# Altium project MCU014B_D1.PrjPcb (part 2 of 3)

## Sheet MCU014B_D1_EngineArea.SchDoc
size 558 x 431 mm; Date: Not shown in title block; ApprovedBy: Not shown in title block; CheckedBy: Not shown in title block; Author: Not shown in title block; CompanyName: Not shown in title block; DrawnBy: Vince Rodriguez; Engineer: Vince Rodriguez; Organization: Not shown in title block; Address1: Not shown in title block; Address2: Not shown in title block; Address3: Not shown in title block; Address4: Not shown in title block; DocumentNumber: 3; Revision: Use project parameter SCH_Rev; SheetNumber: 3; SheetTotal: 7; PageSetup: Record=PageOptions¦CenterHorizontal=True¦CenterVertical=True¦PrintScale=1.00¦XCorrection=1.00¦YCorrection=1.00¦PrintKind=0¦BorderSize=5000000¦LeftOffset=0¦BottomOffset=0¦Orientation=2¦PaperLength=1000¦PaperWidth=1000¦Scale=100¦PaperSource=15¦PrintQuality=600¦MediaType=1¦DitherType=10¦PaperKind=Letter¦PrintScaleMode=1
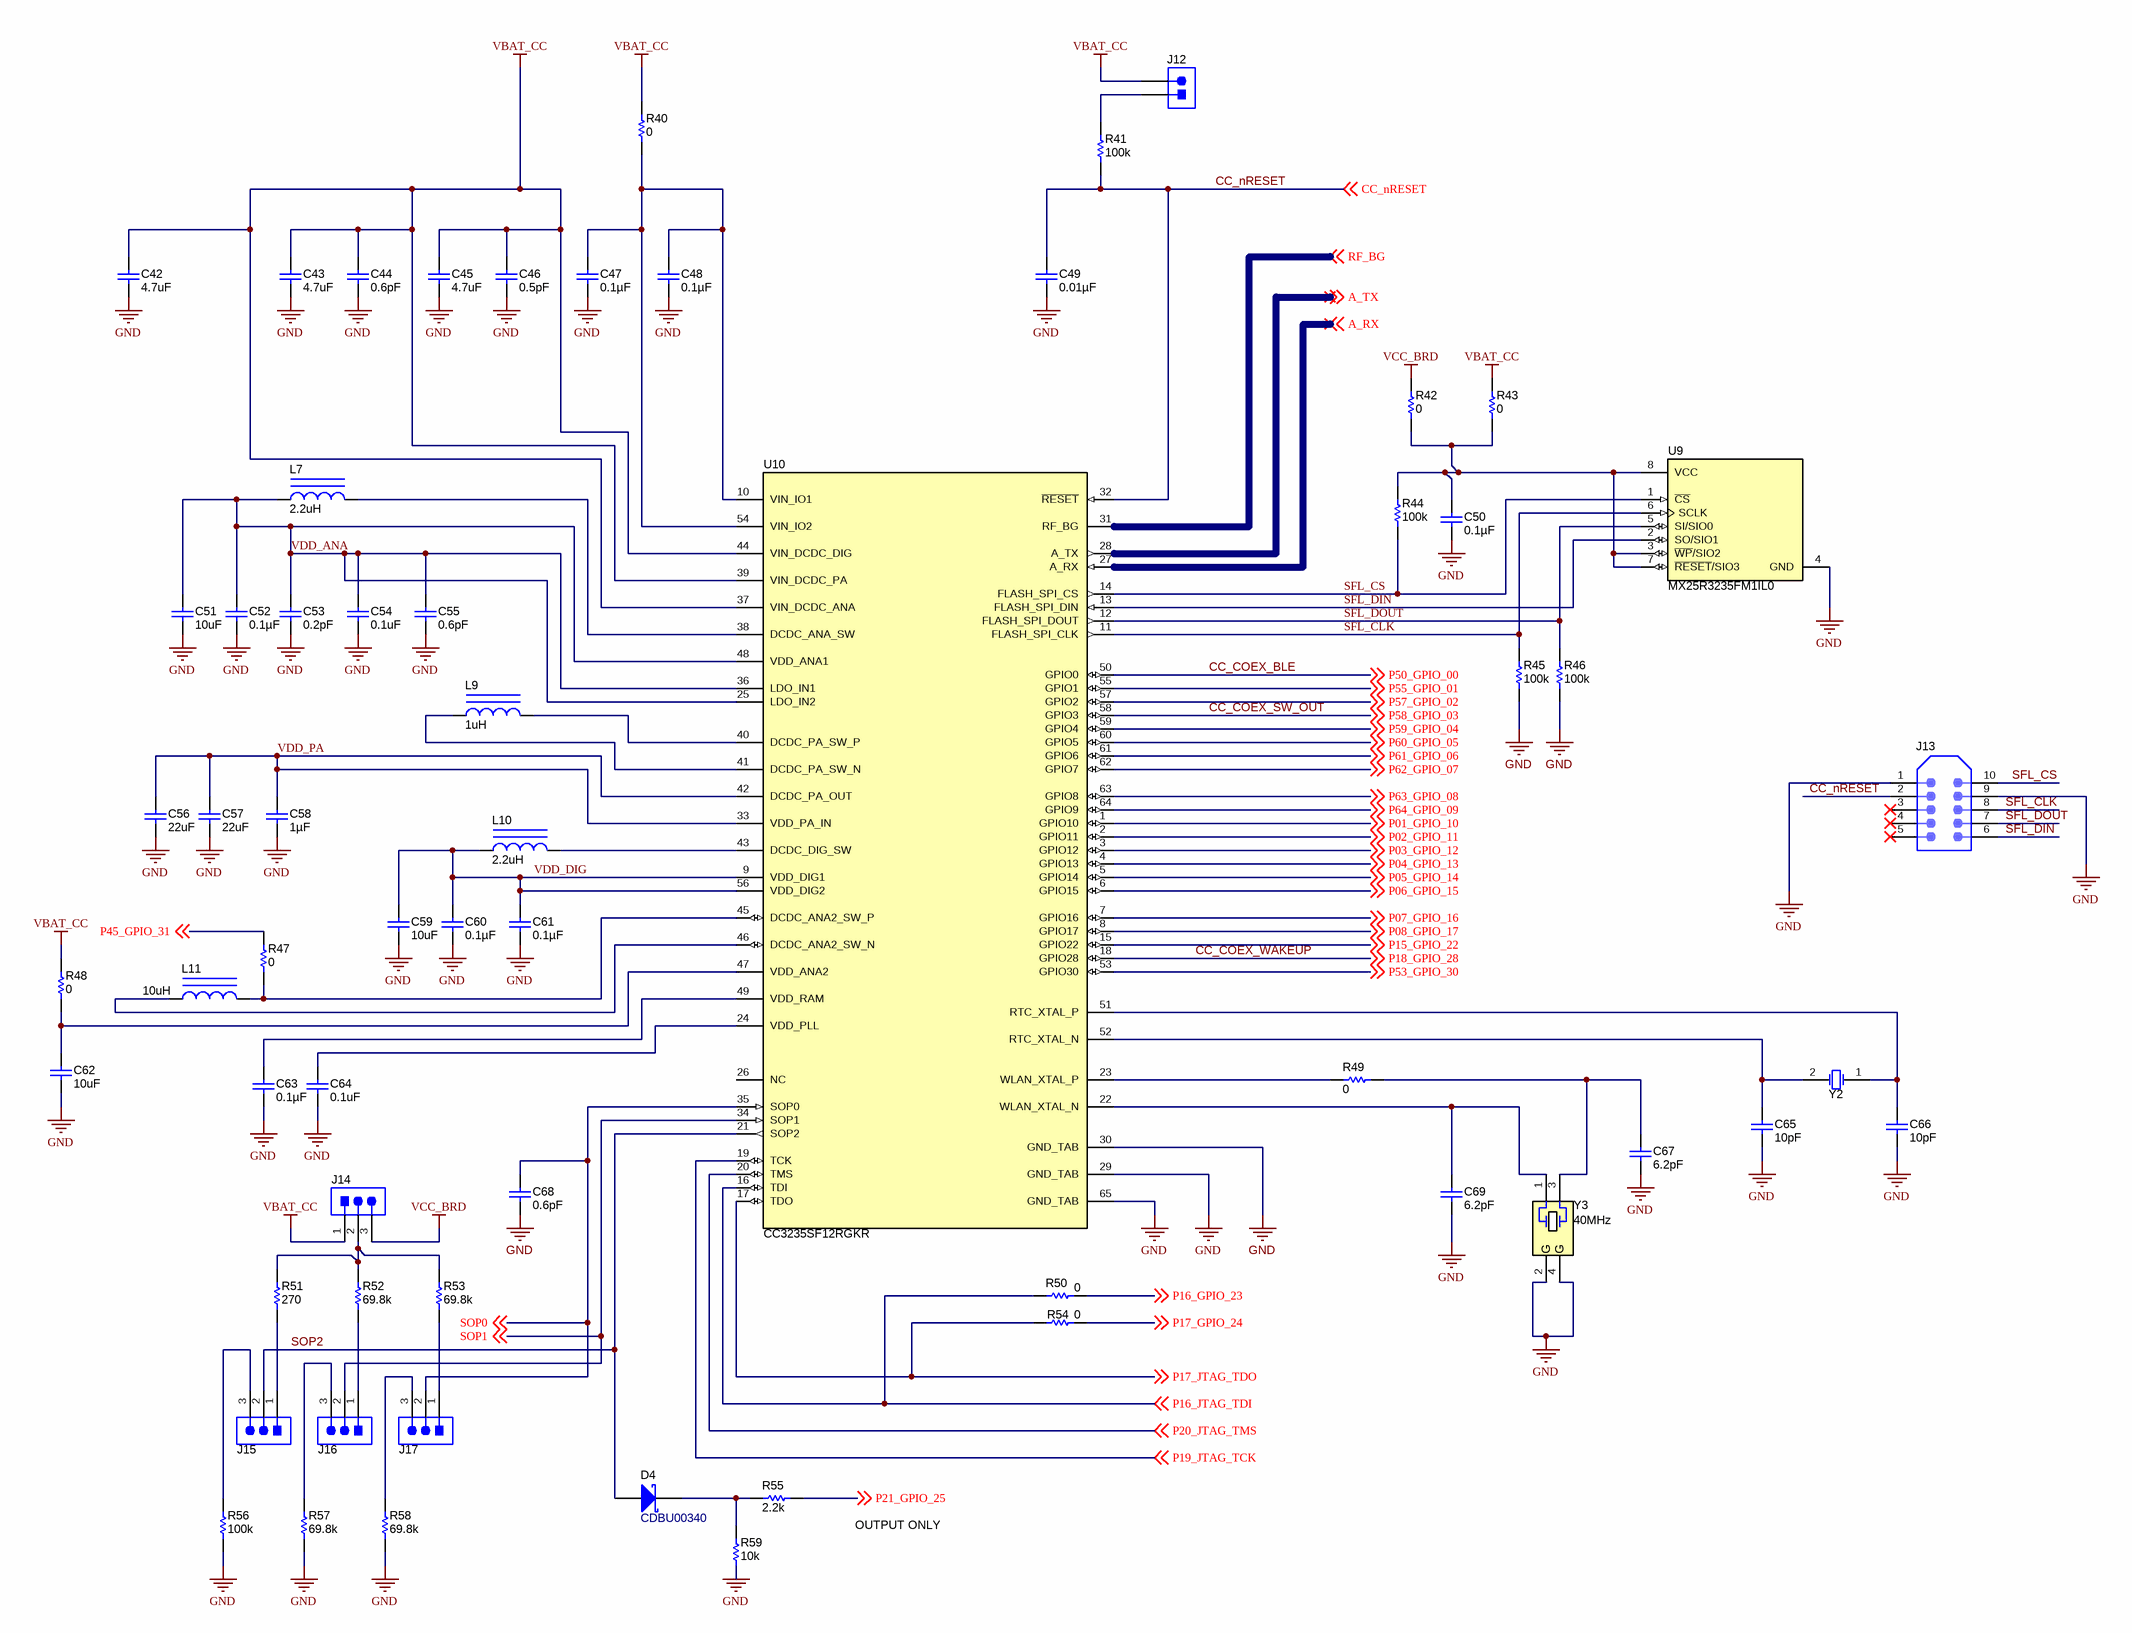
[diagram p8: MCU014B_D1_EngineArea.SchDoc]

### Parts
C42  ValueDisplayed: 4.7uF  [0402]  (hidden comment: CMP-0064972-2)
C43  ValueDisplayed: 4.7uF  [0402]  (hidden comment: CMP-0064972-2)
C44  ValueDisplayed: 0.6pF  [0201_033]  (hidden comment: GJM0335C1ER60BB01D)
C45  ValueDisplayed: 4.7uF  [0402]  (hidden comment: CMP-0064972-2)
C46  ValueDisplayed: 0.5pF  [0201_033]  (hidden comment: GJM0335C1ER50BB01D)
C47  ValueDisplayed: 0.1µF  [0402S]  (hidden comment: CL05B104KO5NNNC)
C48  ValueDisplayed: 0.1µF  [0402S]  (hidden comment: CL05B104KO5NNNC)
C49  ValueDisplayed: 0.01µF  [0402S]  (hidden comment: 0402B103K500CT)
C50  ValueDisplayed: 0.1µF  [0402S]  (hidden comment: CL05B104KO5NNNC)
C51  ValueDisplayed: 10uF  [0603]  (hidden comment: CMP-0064953-4)
C52  ValueDisplayed: 0.1µF  [0402S]  (hidden comment: CL05B104KO5NNNC)
C53  ValueDisplayed: 0.2pF  [0201_033]  (hidden comment: GJM0335C1ER20BB01D)
C54  ValueDisplayed: 0.1uF  [0201]  (hidden comment: CL03A104KP3NNNC)
C55  ValueDisplayed: 0.6pF  [0201_033]  (hidden comment: GJM0335C1ER60BB01D)
C56  ValueDisplayed: 22uF  [0603]  (hidden comment: CMP-0064952-4)
C57  ValueDisplayed: 22uF  [0603]  (hidden comment: CMP-0064952-4)
C58  ValueDisplayed: 1µF  [0402S]  (hidden comment: CL05A105MP5NNNC)
C59  ValueDisplayed: 10uF  [0603]  (hidden comment: CMP-0064953-4)
C60  ValueDisplayed: 0.1µF  [0402S]  (hidden comment: CL05B104KO5NNNC)
C61  ValueDisplayed: 0.1µF  [0402S]  (hidden comment: CL05B104KO5NNNC)
C62  ValueDisplayed: 10uF  [0603]  (hidden comment: CMP-0064953-4)
C63  ValueDisplayed: 0.1µF  [0402S]  (hidden comment: CL05B104KO5NNNC)
C64  ValueDisplayed: 0.1uF  [0201]  (hidden comment: CMP-0009655-3)
C65  ValueDisplayed: 10pF  [0402S]  (hidden comment: 0402N100J500CT)
C66  ValueDisplayed: 10pF  [0402S]  (hidden comment: 0402N100J500CT)
C67  ValueDisplayed: 6.2pF  [0402S]  (hidden comment: 0402N6R2C500CT)
C68  ValueDisplayed: 0.6pF  [0201_033]  (hidden comment: GJM0335C1ER60BB01D)
C69  ValueDisplayed: 6.2pF  [0402S]  (hidden comment: 0402N6R2C500CT)
D4  CDBU00340  [SOD-523F]
J12  CMP-0054794-1  [WURTH_61300211121]  (value not drawn)
J13  TC2050-IDC-NL-FP  [Tag_TC2050-NL]  (value not drawn)  (no BOM)
J14  CMP-0054796-1  [WURTH_61300311121]  (value not drawn)
J15  CMP-0054796-1  [WURTH_61300311121]  (value not drawn)
J16  CMP-0054796-1  [WURTH_61300311121]  (value not drawn)
J17  CMP-0054796-1  [WURTH_61300311121]  (value not drawn)
L7  ValueDisplayed: 2.2uH  [LQM2MPN_G0]  (hidden comment: CMP-0058761-1)
L9  ValueDisplayed: 1uH  [1008]  (hidden comment: CMP-0058750-1)
L10  ValueDisplayed: 2.2uH  [LQM2MPN_G0]  (hidden comment: CMP-0058761-1)
L11  ValueDisplayed: 10uH  [MLP2520S-M]  (hidden comment: CMP-0062710-1)
R40  ValueDisplayed: 0  [0603]  (hidden comment: CMP-0025874-3)
R41  ValueDisplayed: 100k  [0402]  (hidden comment: CMP-0026823-3)
R42  ValueDisplayed: 0  [0402]  (hidden comment: CMP-0026992-2)
R43  ValueDisplayed: 0  [0402]  (hidden comment: CMP-0026992-2)
R44  ValueDisplayed: 100k  [0402]  (hidden comment: CMP-0026823-3)
R45  ValueDisplayed: 100k  [0402]  (hidden comment: CMP-0026823-3)
R46  ValueDisplayed: 100k  [0402]  (hidden comment: CMP-0026823-3)
R47  ValueDisplayed: 0  [0402]  (hidden comment: CMP-0026992-2)
R48  ValueDisplayed: 0  [0402]  (hidden comment: CMP-0026992-2)
R49  ValueDisplayed: 0  [0402]  (hidden comment: CMP-0026992-2)
R50  ValueDisplayed: 0  [0402]  (hidden comment: CMP-0026992-2)
R51  ValueDisplayed: 270  [0402]  (hidden comment: CMP-0026886-3)
R52  ValueDisplayed: 69.8k  [0402]  (hidden comment: CMP-0026510-2)
R53  ValueDisplayed: 69.8k  [0402]  (hidden comment: CMP-0026510-2)
R54  ValueDisplayed: 0  [0402]  (hidden comment: CMP-0026992-2)
R55  ValueDisplayed: 2.2k  [0402]  (hidden comment: CMP-0026890-5)
R56  ValueDisplayed: 100k  [0402]  (hidden comment: CMP-0026823-3)
R57  ValueDisplayed: 69.8k  [0402]  (hidden comment: CMP-0026510-2)
R58  ValueDisplayed: 69.8k  [0402]  (hidden comment: CMP-0026510-2)
R59  ValueDisplayed: 10k  [0402]  (hidden comment: CMP-0026825-5)
U9  PartNumber: MX25R3235FM1IL0  [SOP-8_150MIL]  (hidden comment: CMP-0004903-1)
U10  CC3235SF12RGKR  [RGK0064B]
Y2  CMP-0004575-3  [XTAL_ABS07]  (value not drawn)
Y3  Frequency_Fixed: 40MHz  [TXC_8Y]  (hidden comment: 8Y40072002)

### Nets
GND: C42.2 C43.2 C44.2 C45.2 C46.2 C47.2 C48.2 C49.2 C50.2 C51.2 C52.2 C53.2 C54.2 C55.2 C56.2 C57.2 C58.2 C59.2 C60.2 C61.2 C62.2 C63.2 C64.2 C65.2 C66.2 C67.2 C68.2 C69.2 J13.1 J13.9 R45.2 R46.2 R56.2 R57.2 R58.2 R59.2 U9.4(GND) U10.29(GND_TAB) U10.30(GND_TAB) U10.65(GND_TAB) Y3.2(GND) Y3.4(GND)
VBAT_CC: C42.1 C43.1 C44.1 C45.1 C46.1 J12.2 J14.1 R40.2 R43.2 R48.2 U10.37(VIN_DCDC_ANA) U10.39(VIN_DCDC_PA) U10.44(VIN_DCDC_DIG)
VCC_BRD: J14.3 R42.2
A_RX: U10.27(A_RX) ; off-sheet A_RX
A_TX: U10.28(A_TX) ; off-sheet A_TX
CC_COEX_BLE: U10.50(GPIO0) ; off-sheet P50_GPIO_00  [also labelled P50_GPIO_00]
CC_COEX_SW_OUT: U10.58(GPIO3) ; off-sheet P58_GPIO_03  [also labelled P58_GPIO_03]
CC_COEX_WAKEUP: U10.18(GPIO28) ; off-sheet P18_GPIO_28  [also labelled P18_GPIO_28]
CC_nRESET: C49.1 J13.2 R41.2 U10.32(~{RESET}) ; off-sheet CC_nRESET
P01_GPIO_10: U10.1(GPIO10) ; off-sheet P01_GPIO_10
P02_GPIO_11: U10.2(GPIO11) ; off-sheet P02_GPIO_11
P03_GPIO_12: U10.3(GPIO12) ; off-sheet P03_GPIO_12
P04_GPIO_13: U10.4(GPIO13) ; off-sheet P04_GPIO_13
P05_GPIO_14: U10.5(GPIO14) ; off-sheet P05_GPIO_14
P06_GPIO_15: U10.6(GPIO15) ; off-sheet P06_GPIO_15
P07_GPIO_16: U10.7(GPIO16) ; off-sheet P07_GPIO_16
P08_GPIO_17: U10.8(GPIO17) ; off-sheet P08_GPIO_17
P15_GPIO_22: U10.15(GPIO22) ; off-sheet P15_GPIO_22
P16_GPIO_23: R50.2 ; off-sheet P16_GPIO_23
P16_JTAG_TDI: R50.1 U10.16(TDI) ; off-sheet P16_JTAG_TDI
P17_GPIO_24: R54.2 ; off-sheet P17_GPIO_24
P17_JTAG_TDO: R54.1 U10.17(TDO) ; off-sheet P17_JTAG_TDO
P19_JTAG_TCK: U10.19(TCK) ; off-sheet P19_JTAG_TCK
P20_JTAG_TMS: U10.20(TMS) ; off-sheet P20_JTAG_TMS
P21_GPIO_25: R55.2 ; off-sheet P21_GPIO_25
P45_GPIO_31: R47.1 ; off-sheet P45_GPIO_31
P53_GPIO_30: U10.53(GPIO30) ; off-sheet P53_GPIO_30
P55_GPIO_01: U10.55(GPIO1) ; off-sheet P55_GPIO_01
P57_GPIO_02: U10.57(GPIO2) ; off-sheet P57_GPIO_02
P59_GPIO_04: U10.59(GPIO4) ; off-sheet P59_GPIO_04
P60_GPIO_05: U10.60(GPIO5) ; off-sheet P60_GPIO_05
P61_GPIO_06: U10.61(GPIO6) ; off-sheet P61_GPIO_06
P62_GPIO_07: U10.62(GPIO7) ; off-sheet P62_GPIO_07
P63_GPIO_08: U10.63(GPIO8) ; off-sheet P63_GPIO_08
P64_GPIO_09: U10.64(GPIO9) ; off-sheet P64_GPIO_09
RF_BG: U10.31(RF_BG) ; off-sheet RF_BG
SFL_CLK: J13.8 R45.1 U9.6(SCLK) U10.11(FLASH_SPI_CLK)
SFL_CS: J13.10 R44.2 U9.1(~{CS}) U10.14(FLASH_SPI_CS)
SFL_DIN: J13.6 U9.2(SO/SIO1) U10.13(FLASH_SPI_DIN)
SFL_DOUT: J13.7 R46.1 U9.5(SI/SIO0) U10.12(FLASH_SPI_DOUT)
SOP0: C68.1 J17.2 U10.35(SOP0) ; off-sheet SOP0
SOP1: J16.2 U10.34(SOP1) ; off-sheet SOP1
SOP2: D4.2(A) J15.2 U10.21(SOP2)
VDD_ANA: C51.1 C52.1 C53.1 C54.1 C55.1 L7.1 U10.25(LDO_IN2) U10.36(LDO_IN1) U10.48(VDD_ANA1)
VDD_DIG: C59.1 C60.1 C61.1 L10.1 U10.9(VDD_DIG1) U10.56(VDD_DIG2)
VDD_PA: C56.1 C57.1 C58.1 U10.33(VDD_PA_IN) U10.42(DCDC_PA_OUT)
NetC47_1: C47.1 C48.1 R40.1 U10.10(VIN_IO1) U10.54(VIN_IO2)
NetC50_1: C50.1 R42.1 R43.1 R44.1 U9.3(~{WP}/SIO2) U9.7(~{RESET}/SIO3) U9.8(VCC)
NetC62_1: C62.1 R48.1 U10.47(VDD_ANA2)
NetC63_1: C63.1 U10.49(VDD_RAM)
NetC64_1: C64.1 U10.24(VDD_PLL)
NetC65_1: C65.1 U10.52(RTC_XTAL_N) Y2.2(OSC2)
NetC66_1: C66.1 U10.51(RTC_XTAL_P) Y2.1(OSC1)
NetC67_1: C67.1 R49.1 Y3.3
NetC69_1: C69.1 U10.22(WLAN_XTAL_N) Y3.1
NetD4_1: D4.1(K) R55.1 R59.1
NetJ12_1: J12.1 R41.1
NetJ14_2: J14.2 R51.1 R52.1 R53.1
NetJ15_1: J15.1 R51.2
NetJ15_3: J15.3 R56.1
NetJ16_1: J16.1 R52.2
NetJ16_3: J16.3 R57.1
NetJ17_1: J17.1 R53.2
NetJ17_3: J17.3 R58.1
NetL7_2: L7.2 U10.38(DCDC_ANA_SW)
NetL9_1: L9.1 U10.41(DCDC_PA_SW_N)
NetL9_2: L9.2 U10.40(DCDC_PA_SW_P)
NetL10_2: L10.2 U10.43(DCDC_DIG_SW)
NetL11_1: L11.1 U10.46(DCDC_ANA2_SW_N)
NetL11_2: L11.2 R47.2 U10.45(DCDC_ANA2_SW_P)
NetR49_2: R49.2 U10.23(WLAN_XTAL_P)

Not connected (* = marked no-connect by the designer): J13 3* 4* 5*; U10 26(NC)

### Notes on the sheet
- OUTPUT ONLY

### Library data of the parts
C42 C43 C45 = CMP-0064972-2: CAP, CERM, 4.7 uF, 6.3 V,+/- 20%, X6S, 0402; PartNumber: JMK105BC6475MV-F; Manufacturer: Taiyo Yuden; Alternate PartNumber: CL05A475MQ5NRNC; Alternate Manufacturer: SAMSUNG; Polarized: N; CompType: Capacitor; Value: 4.7uF; U/M: EA; Cap_F: 4.7µF; Value1: Unknown; VDC_V: 6.3V; TaMin_C: -55°C; TaMax_C: 105°C; SizeArea_mm2: 0.5; SizeAreaWB_mm2: 3; SizeX_mm: 1; SizeZ_mm: 0.6; AEC Category: Q200
C44 C55 C68 = CMP-0085407-1: CAP, CERM, 0.6pF, 25 V,+/- 16%, C0G/NP0, 0201; Manufacturer: MuRata; Polarized: N; U/M: EA; VDC_V: 25V; TaMin_C: -55°C; TaMax_C: 125°C; Cap_Case: 0201; SizeArea_mm2: 0.18; SizeAreaWB_mm2: 2.08; SizeX_mm: 0.6; SizeY_mm: 0.3; SizeZ_mm: 0.33; AEC Category: Q200
C46 = CMP-0085408-1: CAP, CERM, 0.5 pF, 25 V,+/- 20%, C0G/NP0, 0201; Manufacturer: MuRata; Polarized: N; Value: 0.5pF; U/M: EA; VDC_V: 25V; TaMin_C: -55°C; TaMax_C: 125°C; Cap_Case: 0201; SizeArea_mm2: 0.18; SizeAreaWB_mm2: 2.08; SizeX_mm: 0.6; SizeY_mm: 0.3; SizeZ_mm: 0.33; AEC Category: Q200
C47 C48 C50 C52 C60 C61 C63 = CMP-0085850-1: CAP, CERM, 0.1 µF, 16 V,+/- 10%, X7R, 0402; Manufacturer: Walsin; Alternate PartNumber: C1005X5R1A104K050BA; Polarized: N; Value: 0.1uF; U/M: EA; Cap_F: 100nF; VDC_V: 16V; TaMin_C: -55°C; TaMax_C: 125°C; Cap_Case: 0402; SizeArea_mm2: 0.5; SizeAreaWB_mm2: 3; SizeX_mm: 1; SizeZ_mm: 0.6; AEC Category: Q200
C49 = CMP-0085842-1: CAP, CERM, 0.01 µF, 50 V,+/- 10%, X7R, 0402; Manufacturer: Walsin; Alternate PartNumber: GRM155R71E103KA01D; Polarized: N; Value: 0.01uF; U/M: EA; Cap_F: 10nF; VDC_V: 50V; TaMin_C: -55°C; TaMax_C: 125°C; Cap_Case: 0402; SizeArea_mm2: 0.5; SizeAreaWB_mm2: 3; SizeX_mm: 1; SizeZ_mm: 0.6; AEC Category: Q200
C51 C59 C62 = CMP-0064953-4: CAP, CERM, 10 uF, 10 V,+/- 20%, X6S, 0603; PartNumber: LMK107BC6106MA-T; Manufacturer: Taiyo Yuden; Alternate PartNumber: CL10A106MP8NNNC; Alternate Manufacturer: SAMSUNG; Polarized: N; CompType: Capacitor; Value: 10uF; U/M: EA; Cap_F: 10µF; Value1: Unknown; VDC_V: 10V; TaMin_C: -55°C; TaMax_C: 105°C; SizeArea_mm2: 1.28; SizeAreaWB_mm2: 4.68; SizeX_mm: 1.6; SizeY_mm: 0.8; SizeZ_mm: 1; AEC Category: Q200
C53 = CMP-0085602-1: CAP, CERM, 0.2pF, 25 V,+/- 50%, C0G/NP0, 0201; Manufacturer: MuRata; Polarized: N; U/M: EA; VDC_V: 25V; TaMin_C: -55°C; TaMax_C: 125°C; Cap_Case: 0201; SizeArea_mm2: 0.18; SizeAreaWB_mm2: 2.08; SizeX_mm: 0.6; SizeY_mm: 0.3; SizeZ_mm: 0.33; AEC Category: Q200
C54 = CMP-0009655-3: CAP, CERM, 0.1 uF, 10 V, +/- 10%, X5R, 0201; Manufacturer: Samsung Electro-Mechanics; Polarized: N; Value: 0.1uF; U/M: EA; Cap_F: 100nF; Value1: Unknown; VDC_V: 10V; TaMin_C: -55°C; TaMax_C: 85°C; SizeArea_mm2: 0.18; SizeAreaWB_mm2: 2.08; SizeX_mm: 0.6; SizeY_mm: 0.3; SizeZ_mm: 0.26; AEC Category: Q200
C56 C57 = CMP-0064952-4: CAP, CERM, 22 uF, 4 V,+/- 20%, X6S, 0603; PartNumber: GRM188C80G226ME15J; Manufacturer: MuRata; Alternate PartNumber: CL10A226MQ8NRNC; Alternate Manufacturer: SAMSUNG; Polarized: N; CompType: Capacitor; Value: 22uF; U/M: EA; Cap_F: 22µF; Value1: Unknown; VDC_V: 4V; TaMin_C: -55°C; TaMax_C: 105°C; SizeArea_mm2: 1.28; SizeAreaWB_mm2: 4.68; SizeX_mm: 1.6; SizeY_mm: 0.8; SizeZ_mm: 1; AEC Category: Q200
C58 = CMP-0085849-1: CAP, CERM, 1 µF, 10 V,+/- 20%, X5R, 0402; Manufacturer: Walsin; Alternate PartNumber: GRM155C81A105KA12D; Polarized: N; Value: 1uF; U/M: EA; VDC_V: 10V; TaMin_C: -55°C; TaMax_C: 85°C; Cap_Case: 0402; SizeArea_mm2: 0.5; SizeAreaWB_mm2: 3; SizeX_mm: 1; SizeZ_mm: 0.6; AEC Category: Q200
C64 = CMP-0009655-3: CAP, CERM, 0.1 uF, 10 V, +/- 10%, X5R, 0201; PartNumber: CL03A104KP3NNNC; Manufacturer: Samsung Electro-Mechanics; Polarized: N; Value: 0.1uF; U/M: EA; Cap_F: 100nF; Value1: Unknown; VDC_V: 10V; TaMin_C: -55°C; TaMax_C: 85°C; SizeArea_mm2: 0.18; SizeAreaWB_mm2: 2.08; SizeX_mm: 0.6; SizeY_mm: 0.3; SizeZ_mm: 0.26; AEC Category: Q200
C65 C66 = CMP-0085843-1: CAP, CERM, 10 pF, 50 V,+/- 5%, C0G/NP0, 0402; Manufacturer: Walsin; Alternate PartNumber: GRM1555C1H100JA01D; Polarized: N; Value: 10pF; U/M: EA; VDC_V: 50V; TaMin_C: -55°C; TaMax_C: 125°C; Cap_Case: 0402; SizeAreaWB_mm2: 3; SizeZ_mm: 0.6; SizeX_mm: 1; SizeY_mm: 0.5; AEC Category: Q200
C67 C69 = CMP-0085844-1: CAP, CERM, 6.2 pF, 50 V,+/- 4%, C0G/NP0, 0402; Manufacturer: Walsin; Alternate PartNumber: GRM1555C1H6R2CA01D; Polarized: N; Value: 6.2pF; U/M: EA; VDC_V: 50V; TaMin_C: -55°C; TaMax_C: 125°C; Cap_Case: 0402; SizeAreaWB_mm2: 3; SizeZ_mm: 0.6; SizeX_mm: 1; SizeY_mm: 0.5; AEC Category: Q200
D4 = CMP-0081923-2: Diode, Schottky, 45 V, 0.03 A, SOD-523F; Manufacturer: Comchip Technology; Alternate PartNumber: CD0603-B00340; Vf_V: 370mV; Value: 45V; Value1: 0.03A; Value2: 0.37V; Io_A: 30mA; TJmax_C: 125°C; AEC Category: Q101; AEC Qualified: N; SizeAreaWB_mm2: 5.13; SizeZ_mm: 0.85; SizeX_mm: 1.7; SizeY_mm: 0.9; SizeArea_mm2: 1.53
J12 = CMP-0054794-1: Header, 2.54 mm, 2x1, Gold, TH; PartNumber: 61300211121; Manufacturer: Wurth Elektronik; Alternate Manufacturer: ----; CNHeader: TRUE; Green_Lifecycle: Active; Green_REACh: Passed; CT: FALSE
J13 = CMP-0075101-1: Footprint for Tag-Connect TC2050 No-Legs cables; CompType: Receptacle; Note: Footprint only, to mate with Tag-Connect TC2050 No-Legs cables; CT: False
J14-J17 = CMP-0054796-1: Header, 2.54 mm, 3x1, Gold, TH; PartNumber: 61300311121; Manufacturer: Wurth Elektronik; Alternate Manufacturer: ----; CNHeader: TRUE; Green_Lifecycle: Active; Green_REACh: Passed; CT: FALSE
L7 L10 = CMP-0058761-1: Inductor, Multilayer, Ferrite, 2.2 uH, 1.2 A, 0.11 ohm, SMD; PartNumber: LQM2MPN2R2NG0; Manufacturer: MuRata; Alternate PartNumber: ----; Value: 2.2uH; Ind_H: 2.2µH; Imax_A: 1.2A; Irms: 1.2A @ 40C rise; DCR_ohm: 1.1d; SizeAreaWB_mm2: 7.8; SizeArea_mm2: 3.2; SizeX_mm: 2; SizeY_mm: 1.6; SizeZ_mm: 1; AEC Category: Q200; AEC Qualified: N
L9 = CMP-0058750-1: Inductor, Multilayer, Ferrite, 1 uH, 1.6 A, 0.055 ohm, SMD; PartNumber: LQM2HPN1R0MG0L; Manufacturer: MuRata; Alternate PartNumber: ----; Value: 1uH; Ind_H: 1µH; Imax_A: 1.6A; Irms: 1.6A @ 40C rise; DCR_ohm: 0.055; Green_Lifecycle: Active; SizeAreaWB_mm2: 10.5; Green_REACh: Passed; SizeZ_mm: 1.2; SizeX_mm: 2.5; SizeY_mm: 2; SizeArea_mm2: 5; AEC Category: Q200
L11 = CMP-0062710-1: Inductor, Multilayer, Ferrite, 10 uH, 0.7 A, 0.364 ohm, SMD; PartNumber: MLP2520S100MT0S1; Manufacturer: TDK; Alternate PartNumber: ----; Value: 10uH; Ind_H: 10µH; Imax_A: 7dA; Irms: 0.7A @ 40C rise; DCR_ohm: 3.64d; Value2: 0.7A; SizeAreaWB_mm2: 11.84; SizeArea_mm2: 5.94; SizeX_mm: 2.7; SizeY_mm: 2.2; SizeZ_mm: 1; AEC Category: Q200; AEC Qualified: N
R40 = CMP-0025874-3: RES, 0, 5%, 0.1 W, 0603; PartNumber: ERJ-3GEY0R00V; Manufacturer: Panasonic; Alternate Manufacturer: YAGEO; Alternate PartNumber: RC0603FR-070RL; Value: 0; Value_Code: 0000; Power_W: 100mW; Value2: 0.1W; VDC_V: 50V; TempCo: 600 ppm/C; EIA_Code: E24; U/M: EA; SizeX_mm: 1.6; SizeY_mm: 0.8; SizeZ_mm: 1; SizeArea_mm2: 1.28; AEC Category: Q200
R41 = CMP-0026823-3: RES, 100 k, 5%, 0.063 W, AEC-Q200 Grade 0, 0402; PartNumber: CRCW0402100KJNED; Manufacturer: Vishay-Dale; Alternate Manufacturer: YAGEO; Alternate PartNumber: RC0402JR-07100KL; Value: 100k; Power_W: 63mW; Value2: 0.063W; VDC_V: 50V; TempCo: 200 ppm/C; EIA_Code: E24; SizeArea_mm2: 0.5; SizeX_mm: 1; SizeZ_mm: 0.6; AEC Category: Q200; AEC Qualified: Y; AEC Grade: 0
R42 R43 R54 = CMP-0026992-2: RES, 0, 5%, 0.063 W, 0402; PartNumber: ERJ-2GE0R00X; Manufacturer: Panasonic; Alternate Manufacturer: YAGEO; Alternate PartNumber: RC0402JR-070RL; Value: 0; Value_Code: 0000; Power_W: 63mW; Value2: 0.063W; VDC_V: 50V; TempCo: 600 ppm/C; EIA_Code: E24; U/M: EA; AEC Category: Q200; SizeX_mm: 1; SizeY_mm: 0.5; SizeZ_mm: 0.6
R44-R46 R56 = CMP-0026823-3: RES, 100 k, 5%, 0.063 W, AEC-Q200 Grade 0, 0402; PartNumber: CRCW0402100KJNED; Manufacturer: Vishay-Dale; Alternate Manufacturer: YAGEO; Alternate PartNumber: RC0402JR-07100KL; Value: 100k; Power_W: 63mW; Value2: 0.063W; VDC_V: 50V; TempCo: 200 ppm/C; EIA_Code: E24; SizeX_mm: 1; SizeY_mm: 0.5; SizeZ_mm: 0.6; AEC Qualified: Y; AEC Category: Q200; AEC Grade: 0
R47-R50 = CMP-0026992-2: RES, 0, 5%, 0.063 W, 0402; PartNumber: ERJ-2GE0R00X; Manufacturer: Panasonic; Alternate Manufacturer: YAGEO; Alternate PartNumber: RC0402JR-070RL; Value: 0; Value_Code: 0000; Power_W: 63mW; Value2: 0.063W; VDC_V: 50V; TempCo: 600 ppm/C; EIA_Code: E24; U/M: EA; SizeX_mm: 1; SizeY_mm: 0.5; SizeZ_mm: 0.6; AEC Category: Q200
R51 = CMP-0026886-3: RES, 270, 5%, 0.063 W, AEC-Q200 Grade 0, 0402; PartNumber: CRCW0402270RJNED; Manufacturer: Vishay-Dale; Alternate Manufacturer: YAGEO; Alternate PartNumber: RC0402JR-07270RL; CompType: Resistor; Value: 270; Value_Code: 270R; Power_W: 63mW; Value2: 0.063W; VDC_V: 50V; TempCo: 200 ppm/C; EIA_Code: E24; SizeX_mm: 1; SizeY_mm: 0.5; SizeZ_mm: 0.6; AEC Qualified: Y; AEC Category: Q200; AEC Grade: 0
R52 R53 R57 R58 = CMP-0026510-2: RES, 69.8 k, 1%, 0.063 W, AEC-Q200 Grade 0, 0402; PartNumber: CRCW040269K8FKED; Manufacturer: Vishay-Dale; Alternate Manufacturer: YAGEO; Alternate PartNumber: RC0402FR-0769K8L; Value: 69.8k; Value_Code: 69k8; Power_W: 63mW; Value2: 0.063W; VDC_V: 50V; TempCo: 100 ppm/C; SizeArea_mm2: 0.5; SizeX_mm: 1; SizeZ_mm: 0.6; EIA_Code: E96; AEC Category: Q200; AEC Qualified: Y; AEC Grade: 0
R55 = CMP-0026890-5: RES, 2.2 k, 5%, 0.063 W, AEC-Q200 Grade 0, 0402; PartNumber: CRCW04022K20JNED; Manufacturer: Vishay-Dale; Alternate Manufacturer: YAGEO; Alternate PartNumber: RC0402JR-072K2L; CompType: Resistor; Value: 2.2k; Value_Code: 2k20; Power_W: 63mW; Value2: 0.063W; VDC_V: 50V; TempCo: 200 ppm/C; EIA_Code: E24; AEC Category: Q200; AEC Qualified: Y; AEC Grade: 0; SizeX_mm: 1; SizeY_mm: 0.5; SizeZ_mm: 0.6
R59 = CMP-0026825-5: RES, 10 k, 5%, 0.063 W, AEC-Q200 Grade 0, 0402; PartNumber: CRCW040210K0JNED; Manufacturer: Vishay-Dale; Alternate Manufacturer: YAGEO; Alternate PartNumber: RC0402JR-0710KL; Value: 10k; Value_Code: 10k0; Power_W: 63mW; Value2: 0.063W; VDC_V: 50V; TempCo: 200 ppm/C; EIA_Code: E24; SizeX_mm: 1; SizeY_mm: 0.5; SizeZ_mm: 0.6; AEC Qualified: Y; AEC Category: Q200; AEC Grade: 0
U9 = CMP-0004903-1: ULTRA LOW POWER, 32M-BIT [x 1/x 2/x 4] CMOS MXSMIO(SERIAL MULTI I/O) FLASH MEMORY, SOP-8; Manufacturer: Macronix International Co., LTD; Alternate Manufacturer: ----
U10 = CMP-0065220-6: SimpleLink Wi-Fi and Internet-of-Things Solution, a Single-Chip Wireless MCU, RGK0064B (VQFN-64); Manufacturer: Texas Instruments; CompType: IC; SizeArea_mm2: 81.0; SizeAreaWB_mm2: 121.0; SizeX_mm: 9.0; SizeZ_mm: 1.0; AEC Qualified: N; AEC Category: Q200
Y2 = CMP-0004575-3: CRYSTAL, 32.768KHz, 9PF, SMD; PartNumber: ABS07-32.768KHZ-9-T; Manufacturer: Abracon Corporation; Alternate Manufacturer: ----; TaMin_C: -40°C; TaMax_C: 85°C; Frequency Stability: +/-20ppm
Y3 = CMP-0077111-2: Crystal, 40 MHz, 8 pF, SMD; Manufacturer: TXC Corporation; Alternate Manufacturer: ----; Alternate PartNumber: Order Directly from TXC; TaMax_C: 95°C; TaMin_C: -40°C; U/M: EA; Frequency Stability: ±15ppm

## Sheet MCU014B_D1_HostInterface_ADC.SchDoc
size 558 x 431 mm; Date: Not shown in title block; ApprovedBy: Not shown in title block; CheckedBy: Not shown in title block; Author: Not shown in title block; CompanyName: Not shown in title block; DrawnBy: Vince Rodriguez; Engineer: Vince Rodriguez; Organization: Not shown in title block; Address1: Not shown in title block; Address2: Not shown in title block; Address3: Not shown in title block; Address4: Not shown in title block; DocumentNumber: 4; Revision: Use project parameter SCH_Rev; SheetNumber: 4; SheetTotal: 7; PageSetup: Record=PageOptions¦CenterHorizontal=True¦CenterVertical=True¦PrintScale=1.00¦XCorrection=1.00¦YCorrection=1.00¦PrintKind=0¦BorderSize=5000000¦LeftOffset=0¦BottomOffset=0¦Orientation=2¦PaperLength=1000¦PaperWidth=1000¦Scale=100¦PaperSource=15¦PrintQuality=600¦MediaType=1¦DitherType=10¦PaperKind=Letter¦PrintScaleMode=1
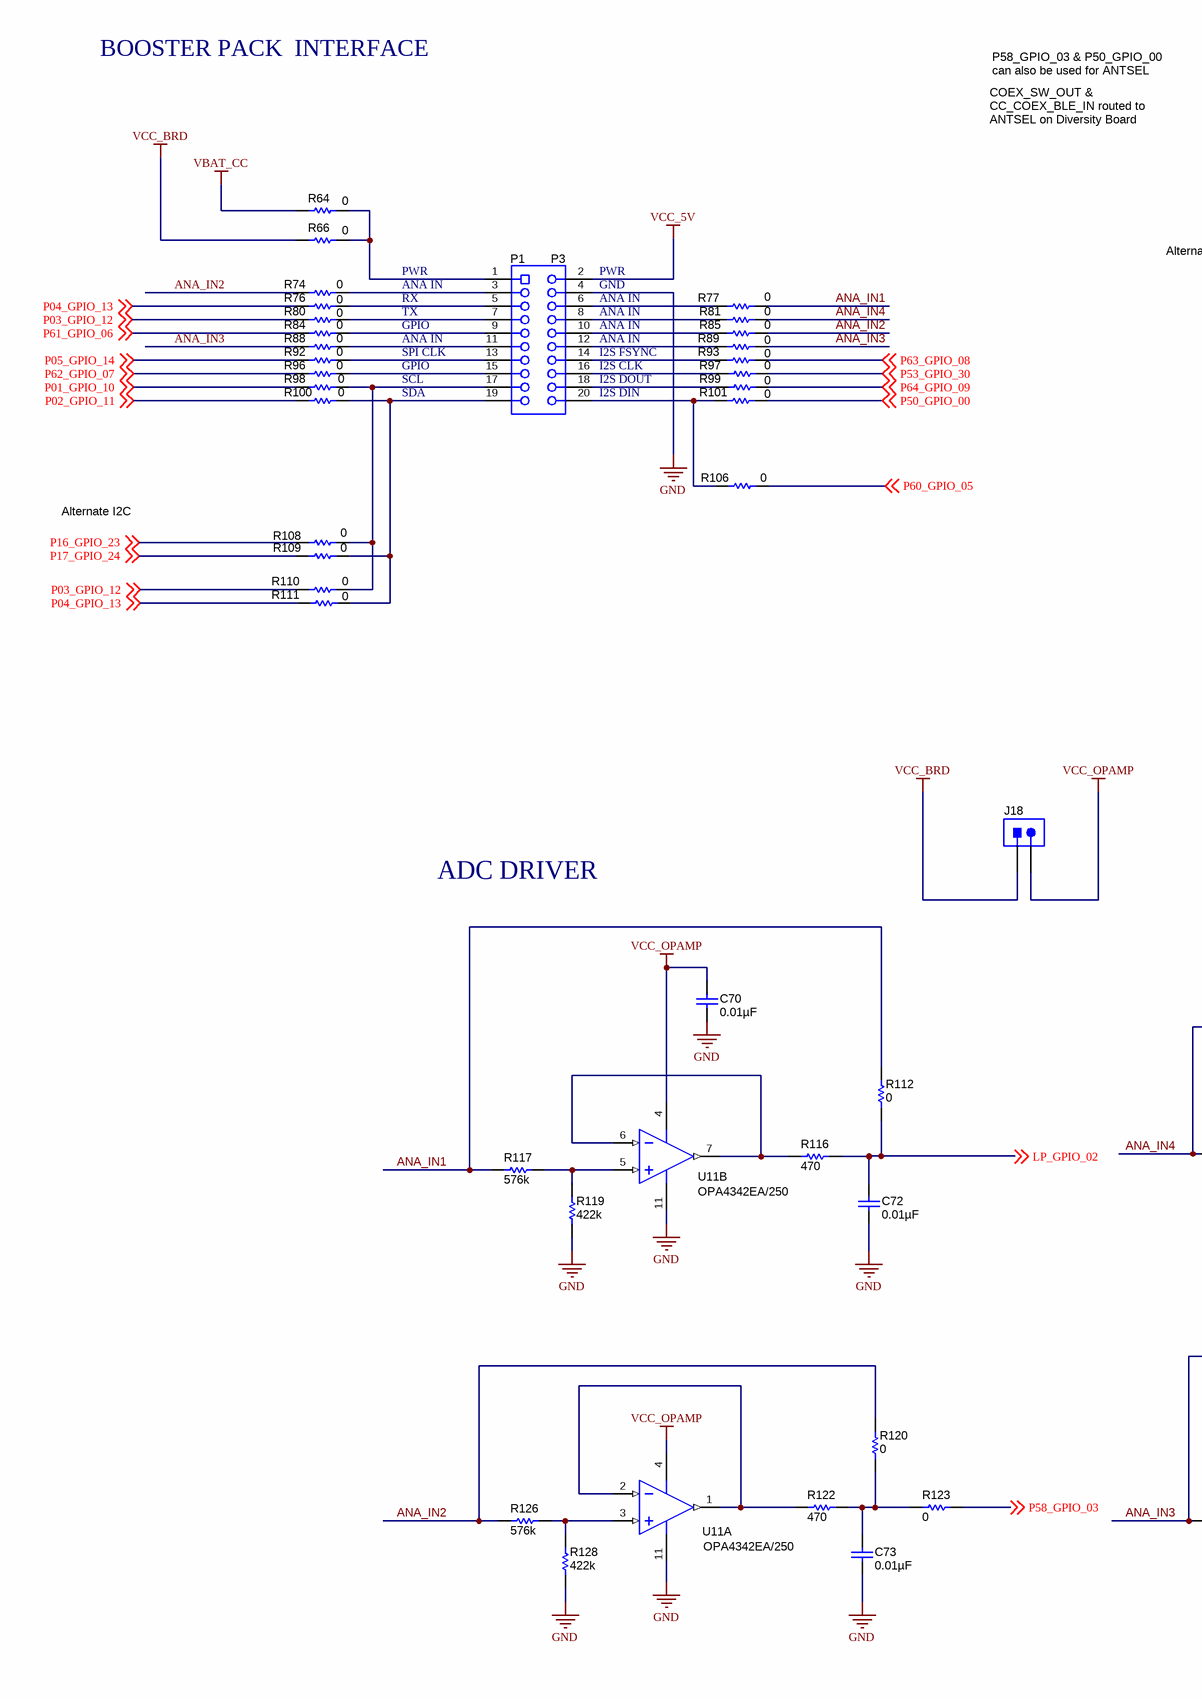
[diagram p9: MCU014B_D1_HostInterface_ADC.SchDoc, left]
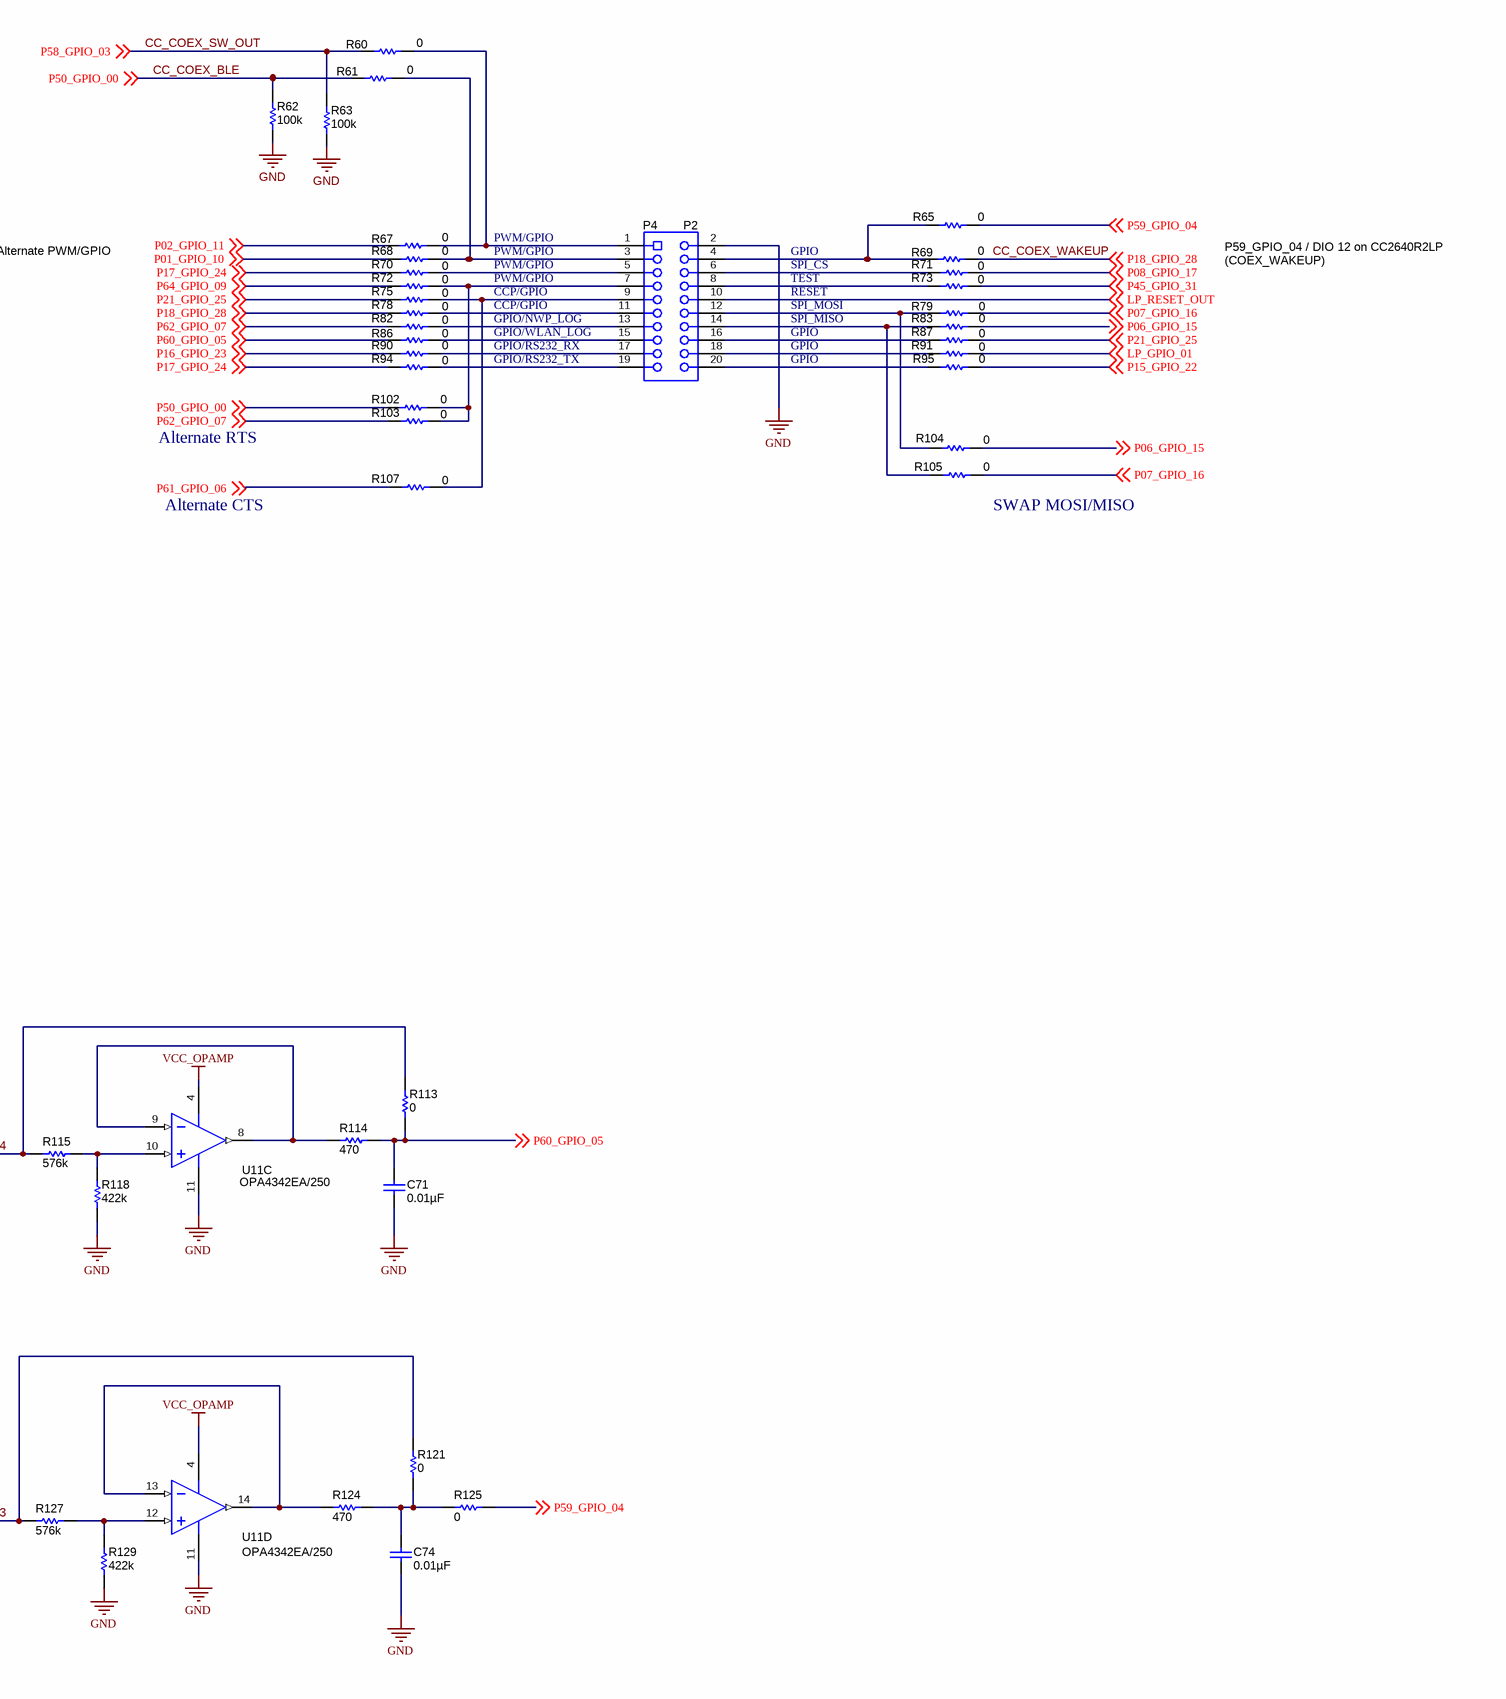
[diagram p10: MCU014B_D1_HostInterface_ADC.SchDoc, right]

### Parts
(Parts that share a designator on the sheet are numbered #1, #2 ... from top to bottom, then left to right.)
C70  ValueDisplayed: 0.01µF  [0402S]  (hidden comment: 0402B103K500CT)
C71  ValueDisplayed: 0.01µF  [0402S]  (hidden comment: 0402B103K500CT)
C72  ValueDisplayed: 0.01µF  [0402S]  (hidden comment: 0402B103K500CT)
C73  ValueDisplayed: 0.01µF  [0402S]  (hidden comment: 0402B103K500CT)
C74  ValueDisplayed: 0.01µF  [0402S]  (hidden comment: 0402B103K500CT)
J18  CMP-0054794-1  [WURTH_61300211121]  (value not drawn)
P1  CRD-081413-A-G  [Major_CRD-081413-A-x]  (value not drawn)
P2  CRD-081413-A-G  [Major_CRD-081413-A-x]  (value not drawn)
R60  ValueDisplayed: 0  [0402]  (hidden comment: CMP-0026992-2)
R61  ValueDisplayed: 0  [0402]  (hidden comment: CMP-0026992-2)
R62  ValueDisplayed: 100k  [0402]  (hidden comment: CMP-0026823-3)
R63  ValueDisplayed: 100k  [0402]  (hidden comment: CMP-0026823-3)
R64  ValueDisplayed: 0  [0603]  (hidden comment: CMP-0025874-3)
R65  ValueDisplayed: 0  [0402]  (hidden comment: CMP-0026992-2)
R66  ValueDisplayed: 0  [0603]  (hidden comment: CMP-0025874-3)
R67  ValueDisplayed: 0  [0402]  (hidden comment: CMP-0026992-2)
R68  ValueDisplayed: 0  [0402]  (hidden comment: CMP-0026992-2)
R69  ValueDisplayed: 0  [0402]  (hidden comment: CMP-0026992-2)
R70  ValueDisplayed: 0  [0402]  (hidden comment: CMP-0026992-2)
R71  ValueDisplayed: 0  [0402]  (hidden comment: CMP-0026992-2)
R72  ValueDisplayed: 0  [0402]  (hidden comment: CMP-0026992-2)
R73  ValueDisplayed: 0  [0402]  (hidden comment: CMP-0026992-2)
R74  ValueDisplayed: 0  [0402]  (hidden comment: CMP-0026992-2)
R75  ValueDisplayed: 0  [0402]  (hidden comment: CMP-0026992-2)
R76  ValueDisplayed: 0  [0402]  (hidden comment: CMP-0026992-2)
R77  ValueDisplayed: 0  [0402]  (hidden comment: CMP-0026992-2)
R78  ValueDisplayed: 0  [0402]  (hidden comment: CMP-0026992-2)
R79  ValueDisplayed: 0  [0402]  (hidden comment: CMP-0026992-2)
R80  ValueDisplayed: 0  [0402]  (hidden comment: CMP-0026992-2)
R81  ValueDisplayed: 0  [0402]  (hidden comment: CMP-0026992-2)
R82  ValueDisplayed: 0  [0402]  (hidden comment: CMP-0026992-2)
R83  ValueDisplayed: 0  [0402]  (hidden comment: CMP-0026992-2)
R84  ValueDisplayed: 0  [0402]  (hidden comment: CMP-0026992-2)
R85  ValueDisplayed: 0  [0402]  (hidden comment: CMP-0026992-2)
R86  ValueDisplayed: 0  [0402]  (hidden comment: CMP-0026992-2)
R87  ValueDisplayed: 0  [0402]  (hidden comment: CMP-0026992-2)
R88  ValueDisplayed: 0  [0402]  (hidden comment: CMP-0026992-2)
R89  ValueDisplayed: 0  [0402]  (hidden comment: CMP-0026992-2)
R90  ValueDisplayed: 0  [0402]  (hidden comment: CMP-0026992-2)
R91  ValueDisplayed: 0  [0402]  (hidden comment: CMP-0026992-2)
R92  ValueDisplayed: 0  [0402]  (hidden comment: CMP-0026992-2)
R93  ValueDisplayed: 0  [0402]  (hidden comment: CMP-0026992-2)
R94  ValueDisplayed: 0  [0402]  (hidden comment: CMP-0026992-2)
R95  ValueDisplayed: 0  [0402]  (hidden comment: CMP-0026992-2)
R96  ValueDisplayed: 0  [0402]  (hidden comment: CMP-0026992-2)
R97  ValueDisplayed: 0  [0402]  (hidden comment: CMP-0026992-2)
R98  ValueDisplayed: 0  [0402]  (hidden comment: CMP-0026992-2)
R99  ValueDisplayed: 0  [0402]  (hidden comment: CMP-0026992-2)
R100  ValueDisplayed: 0  [0402]  (hidden comment: CMP-0026992-2)
R101  ValueDisplayed: 0  [0402]  (hidden comment: CMP-0026992-2)
R102  ValueDisplayed: 0  [0402]  (hidden comment: CMP-0026992-2)
R103  ValueDisplayed: 0  [0402]  (hidden comment: CMP-0026992-2)
R104  ValueDisplayed: 0  [0402]  (hidden comment: CMP-0026992-2)
R105  ValueDisplayed: 0  [0402]  (hidden comment: CMP-0026992-2)
R106  ValueDisplayed: 0  [0402]  (hidden comment: CMP-0026992-2)
R107  ValueDisplayed: 0  [0402]  (hidden comment: CMP-0026992-2)
R108  ValueDisplayed: 0  [0402]  (hidden comment: CMP-0026992-2)
R109  ValueDisplayed: 0  [0402]  (hidden comment: CMP-0026992-2)
R110  ValueDisplayed: 0  [0402]  (hidden comment: CMP-0026992-2)
R111  ValueDisplayed: 0  [0402]  (hidden comment: CMP-0026992-2)
R112  ValueDisplayed: 0  [0402]  (hidden comment: CMP-0026992-2)
R113  ValueDisplayed: 0  [0402]  (hidden comment: CMP-0026992-2)
R114  ValueDisplayed: 470  [0402]  (hidden comment: CMP-0026699-1)
R115  ValueDisplayed: 576k  [0402]  (hidden comment: CMP-0026455-2)
R116  ValueDisplayed: 470  [0402]  (hidden comment: CMP-0026699-1)
R117  ValueDisplayed: 576k  [0402]  (hidden comment: CMP-0026455-2)
R118  ValueDisplayed: 422k  [0402]  (hidden comment: CMP-0026373-2)
R119  ValueDisplayed: 422k  [0402]  (hidden comment: CMP-0026373-2)
R120  ValueDisplayed: 0  [0402]  (hidden comment: CMP-0026992-2)
R121  ValueDisplayed: 0  [0402]  (hidden comment: CMP-0026992-2)
R122  ValueDisplayed: 470  [0402]  (hidden comment: CMP-0026699-1)
R123  ValueDisplayed: 0  [0402]  (hidden comment: CMP-0026992-2)
R124  ValueDisplayed: 470  [0402]  (hidden comment: CMP-0026699-1)
R125  ValueDisplayed: 0  [0402]  (hidden comment: CMP-0026992-2)
R126  ValueDisplayed: 576k  [0402]  (hidden comment: CMP-0026455-2)
R127  ValueDisplayed: 576k  [0402]  (hidden comment: CMP-0026455-2)
R128  ValueDisplayed: 422k  [0402]  (hidden comment: CMP-0026373-2)
R129  ValueDisplayed: 422k  [0402]  (hidden comment: CMP-0026373-2)
U11#1  PartNumber: OPA4342EA/250  [PW0014A_N]  (hidden comment: CMP-0041122-1)  (parts B,C,D of 4)
U11#2  PartNumber: OPA4342EA/250  [PW0014A_N]  (hidden comment: CMP-0041122-1)  (part A of 4)

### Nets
GND: C70.2 C71.2 C72.2 C73.2 C74.2 P1.2 P2.4 R62.2 R63.2 R118.1 R119.1 R128.1 R129.1 U11#1.11(V-) U11#2.11(V-)
VBAT_CC: R64.1
VCC_5V: P2.2
VCC_BRD: J18.1 R66.1
VCC_OPAMP: C70.1 J18.2 U11#1.4(V+) U11#2.4(V+)
ANA_IN1: R77.2 R112.2 R117.1
ANA_IN2: R74.1 R85.2 R120.2 R126.1
ANA_IN3: R88.1 R89.2 R121.2 R127.1
ANA_IN4: R81.2 R113.2 R115.1
CC_COEX_BLE: R61.1 R62.1 R101.2 R102.1 ; off-sheet P50_GPIO_00  [also labelled P50_GPIO_00]
CC_COEX_SW_OUT: R60.1 R63.1 R123.2 ; off-sheet P58_GPIO_03  [also labelled P58_GPIO_03]
CC_COEX_WAKEUP: R69.2 R78.1 ; off-sheet P18_GPIO_28  [also labelled P18_GPIO_28]
LP_GPIO_01: R91.2 ; off-sheet LP_GPIO_01
LP_GPIO_02: C72.1 R112.1 R116.2 ; off-sheet LP_GPIO_02
LP_RESET_OUT: P1.10 ; off-sheet LP_RESET_OUT
P01_GPIO_10: R68.1 R98.1 ; off-sheet P01_GPIO_10
P02_GPIO_11: R67.1 R100.1 ; off-sheet P02_GPIO_11
P03_GPIO_12: R80.1 R110.1 ; off-sheet P03_GPIO_12
P04_GPIO_13: R76.1 R111.1 ; off-sheet P04_GPIO_13
P05_GPIO_14: R92.1 ; off-sheet P05_GPIO_14
P06_GPIO_15: R83.2 R104.2 ; off-sheet P06_GPIO_15
P07_GPIO_16: R79.2 R105.2 ; off-sheet P07_GPIO_16
P08_GPIO_17: R71.2 ; off-sheet P08_GPIO_17
P15_GPIO_22: R95.2 ; off-sheet P15_GPIO_22
P16_GPIO_23: R90.1 R108.1 ; off-sheet P16_GPIO_23
P17_GPIO_24: R70.1 R94.1 R109.1 ; off-sheet P17_GPIO_24
P21_GPIO_25: R75.1 R87.2 ; off-sheet P21_GPIO_25
P45_GPIO_31: R73.2 ; off-sheet P45_GPIO_31
P53_GPIO_30: R97.2 ; off-sheet P53_GPIO_30
P59_GPIO_04: R65.2 R125.2 ; off-sheet P59_GPIO_04
P60_GPIO_05: C71.1 R86.1 R106.2 R113.1 R114.2 ; off-sheet P60_GPIO_05
P61_GPIO_06: R84.1 R107.1 ; off-sheet P61_GPIO_06
P62_GPIO_07: R82.1 R96.1 R103.1 ; off-sheet P62_GPIO_07
P63_GPIO_08: R93.2 ; off-sheet P63_GPIO_08
P64_GPIO_09: R72.1 R99.2 ; off-sheet P64_GPIO_09
NetC73_1: C73.1 R120.1 R122.2 R123.1
NetC74_1: C74.1 R121.1 R124.2 R125.1
NetP1_1: P1.1 R60.2 R67.2
NetP1_3: P1.3 R61.2 R68.2
NetP1_4: P1.4 R65.1 R69.1
NetP1_5: P1.5 R70.2
NetP1_6: P1.6 R71.1
NetP1_7: P1.7 R72.2 R102.2 R103.2
NetP1_8: P1.8 R73.1
NetP1_9: P1.9 R75.2 R107.2
NetP1_11: P1.11 R78.2
NetP1_12: P1.12 R79.1 R104.1
NetP1_13: P1.13 R82.2
NetP1_14: P1.14 R83.1 R105.1
NetP1_15: P1.15 R86.2
NetP1_16: P1.16 R87.1
NetP1_17: P1.17 R90.2
NetP1_18: P1.18 R91.1
NetP1_19: P1.19 R94.2
NetP1_20: P1.20 R95.1
NetP2_1: P2.1 R64.2 R66.2
NetP2_3: P2.3 R74.2
NetP2_5: P2.5 R76.2
NetP2_6: P2.6 R77.1
NetP2_7: P2.7 R80.2
NetP2_8: P2.8 R81.1
NetP2_9: P2.9 R84.2
NetP2_10: P2.10 R85.1
NetP2_11: P2.11 R88.2
NetP2_12: P2.12 R89.1
NetP2_13: P2.13 R92.2
NetP2_14: P2.14 R93.1
NetP2_15: P2.15 R96.2
NetP2_16: P2.16 R97.1
NetP2_17: P2.17 R98.2 R108.2 R110.2
NetP2_18: P2.18 R99.1
NetP2_19: P2.19 R100.2 R109.2 R111.2
NetP2_20: P2.20 R101.1 R106.1
NetR114_1: R114.1 U11#1.8(OUT_C) U11#1.9(IN_C-)
NetR115_2: R115.2 R118.2 U11#1.10(IN_C+)
NetR116_1: R116.1 U11#1.6(IN_B-) U11#1.7(OUT_B)
NetR117_2: R117.2 R119.2 U11#1.5(IN_B+)
NetR122_1: R122.1 U11#2.1(OUT_A) U11#2.2(IN_A-)
NetR124_1: R124.1 U11#1.13(IN_D-) U11#1.14(OUT_D)
NetR126_2: R126.2 R128.2 U11#2.3(IN_A+)
NetR127_2: R127.2 R129.2 U11#1.12(IN_D+)

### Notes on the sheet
- BOOSTER PACK  INTERFACE
- P58_GPIO_03 & P50_GPIO_00 can also be used for ANTSEL
- COEX_SW_OUT & CC_COEX_BLE_IN routed to ANTSEL on Diversity Board
- (near P1) P4
- (near P1) P2
- PWR
- ANA IN
- (near P2) P1
- (near P2) P3
- (near P2) PWR
- (near P2) GND
- Alternate PWM/GPIO
- PWM/GPIO
- GPIO
- SPI_CS
- TEST
- P59_GPIO_04 / DIO 12 on CC2640R2LP (COEX_WAKEUP)
- RX
- TX
- SPI CLK
- (near P2) I2S FSYNC
- (near P2) ANA IN
- CCP/GPIO
- GPIO/NWP_LOG
- GPIO/WLAN_LOG
- GPIO/RS232_RX
- GPIO/RS232_TX
- RESET
- SPI_MOSI
- SPI_MISO
- SCL
- SDA
- (near P2) I2S CLK
- (near P2) I2S DOUT
- (near P2) I2S DIN
- Alternate RTS
- Alternate I2C
- Alternate CTS
- (near R105) SWAP MOSI/MISO
- ADC DRIVER

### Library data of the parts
C70 = CMP-0085842-1: CAP, CERM, 0.01 µF, 50 V,+/- 10%, X7R, 0402; Manufacturer: Walsin; Alternate PartNumber: GRM155R61A103KA01D; Polarized: N; Value: 0.01uF; U/M: EA; Cap_F: 10nF; VDC_V: 50V; TaMin_C: -55°C; TaMax_C: 125°C; Cap_Case: 0402; SizeAreaWB_mm2: 3; SizeZ_mm: 0.6; SizeX_mm: 1; SizeY_mm: 0.5; AEC Category: Q200
C71-C74 = CMP-0085842-1: CAP, CERM, 0.01 µF, 50 V,+/- 10%, X7R, 0402; Manufacturer: Walsin; Alternate PartNumber: C1005X7R1C103K050BA; Polarized: N; Value: 0.01uF; U/M: EA; Cap_F: 10nF; VDC_V: 50V; TaMin_C: -55°C; TaMax_C: 125°C; Cap_Case: 0402; SizeArea_mm2: 0.5; SizeAreaWB_mm2: 3; SizeX_mm: 1; SizeZ_mm: 0.6; AEC Category: Q200
J18 = CMP-0054794-1: as J12 on sheet MCU014B_D1_EngineArea
P1 P2 = CMP-0075108-1: Receptacle, 2.54 mm, 10x2, Gold, TH; Manufacturer: Major League Electronics; Alternate PartNumber: Order Directly from Major League; Green_Lifecycle: Not Set; Green_REACh: Incomplete; CT: False
R60 R61 R65 R67-R111 = CMP-0026992-2: as R47 on sheet MCU014B_D1_EngineArea
R62 R63 = CMP-0026823-3: as R44-R46 on sheet MCU014B_D1_EngineArea
R64 R66 = CMP-0025874-3: RES, 0, 5%, 0.1 W, 0603; PartNumber: ERJ-3GEY0R00V; Manufacturer: Panasonic; Alternate Manufacturer: YAGEO; Alternate PartNumber: RC0603FR-070RL; CompType: Resistor; Value: 0; Value_Code: 0000; Power_W: 100mW; Value2: 0.1W; VDC_V: 50V; TempCo: 600 ppm/C; EIA_Code: E24; U/M: EA; AEC Category: Q200; SizeX_mm: 1.6; SizeY_mm: 0.8; SizeZ_mm: 1; SizeArea_mm2: 1.28
R112 R113 R120 R121 R123 R125 = CMP-0026992-2: as R42 on sheet MCU014B_D1_EngineArea
R114 R116 R122 R124 = CMP-0026699-1: RES, 470, 1%, 0.1 W, AEC-Q200 Grade 0, 0402; PartNumber: ERJ-2RKF4700X; Manufacturer: Panasonic; Alternate Manufacturer: YAGEO; Alternate PartNumber: RC0402FR-07470RL; Value: 470; Value_Code: 470R; Power_W: 100mW; Value2: 0.1W; VDC_V: 50V; TempCo: 100 ppm/C; U/M: EA; SizeX_mm: 1; SizeY_mm: 0.5; SizeZ_mm: 0.6; AEC Qualified: Y; AEC Grade: 0; AEC Category: Q200
R115 R117 R126 R127 = CMP-0026455-2: RES, 576 k, 1%, 0.063 W, AEC-Q200 Grade 0, 0402; PartNumber: CRCW0402576KFKED; Manufacturer: Vishay-Dale; Alternate Manufacturer: YAGEO; Alternate PartNumber: RC0402FR-07576KL; Value: 576k; Power_W: 63mW; Value2: 0.063W; VDC_V: 50V; TempCo: 100 ppm/C; EIA_Code: E96; SizeX_mm: 1; SizeY_mm: 0.5; SizeZ_mm: 0.6; AEC Qualified: Y; AEC Category: Q200; AEC Grade: 0
R118 R119 R128 R129 = CMP-0026373-2: RES, 422 k, 1%, 0.063 W, AEC-Q200 Grade 0, 0402; PartNumber: CRCW0402422KFKED; Manufacturer: Vishay-Dale; Alternate Manufacturer: YAGEO; Alternate PartNumber: RC0402FR-07422KL; Value: 422k; Power_W: 63mW; Value2: 0.063W; VDC_V: 50V; TempCo: 100 ppm/C; EIA_Code: E96; SizeX_mm: 1; SizeY_mm: 0.5; SizeZ_mm: 0.6; AEC Qualified: Y; AEC Category: Q200; AEC Grade: 0
U11#1 = CMP-0041122-1: Low Cost, Low Power, Rail-to-Rail Operational Amplifier MicroAmplifier(TM) Series, 2.7 to 5.5 V, -55 to 125 degC, 14-pin SOP (PW14), Green (RoHS & no Sb/Br); Manufacturer: Texas Instruments; CMRR(Min)(dB): 76; GBW(Typ)(MHz): 1; IIB(Max)(pA): 10; Iq per channel(Max)(mA): 0.25; Number of Channels: 4; Offset Drift(Typ)(uV/C): 3; Packing: SMALL T&R; Rating: Catalog; Sub Family: Low Input Bias Current Amp (<=10pA), Low Power Amp (<=500uA), Low Supply Voltage Amplifier (<=2.7V), Precision Amplifier; Total Supply Voltage(Max)(+5V is 5, +/-5V is 10): 5.5; Total Supply Voltage(Min)(+5V is 5, +/-5V is 10): 2.7; Vio (25C)(Max)(mV): 6
U11#2 = CMP-0041122-1: Low Cost, Low Power, Rail-to-Rail Operational Amplifier MicroAmplifier(TM) Series, 2.7 to 5.5 V, -55 to 125 degC, 14-pin SOP (PW14), Green (RoHS & no Sb/Br); Manufacturer: Texas Instruments; Alternate PartNumber: ----; CMRR(Min)(dB): 76; GBW(Typ)(MHz): 1; IIB(Max)(pA): 10; Iq per channel(Max)(mA): 0.25; Number of Channels: 4; Offset Drift(Typ)(uV/C): 3; Packing: SMALL T&R; Rating: Catalog; Sub Family: Low Input Bias Current Amp (<=10pA), Low Power Amp (<=500uA), Low Supply Voltage Amplifier (<=2.7V), Precision Amplifier; Total Supply Voltage(Max)(+5V is 5, +/-5V is 10): 5.5; Total Supply Voltage(Min)(+5V is 5, +/-5V is 10): 2.7; Vio (25C)(Max)(mV): 6

## Sheet MCU014B_D1_PowerLedsSwitchSensors.SchDoc
size 558 x 431 mm; Date: Not shown in title block; ApprovedBy: Not shown in title block; CheckedBy: Not shown in title block; Author: Not shown in title block; CompanyName: Not shown in title block; DrawnBy: Vince Rodriguez; Engineer: Not shown in title block; Organization: Not shown in title block; Address1: Not shown in title block; Address2: Not shown in title block; Address3: Not shown in title block; Address4: Not shown in title block; DocumentNumber: 5; Revision: Use project parameter SCH_Rev; SheetNumber: 5; SheetTotal: 7; PageSetup: Record=PageOptions¦CenterHorizontal=True¦CenterVertical=True¦PrintScale=1.00¦XCorrection=1.00¦YCorrection=1.00¦PrintKind=0¦BorderSize=5000000¦LeftOffset=0¦BottomOffset=0¦Orientation=2¦PaperLength=1000¦PaperWidth=1000¦Scale=100¦PaperSource=15¦PrintQuality=600¦MediaType=1¦DitherType=10¦PaperKind=Letter¦PrintScaleMode=1
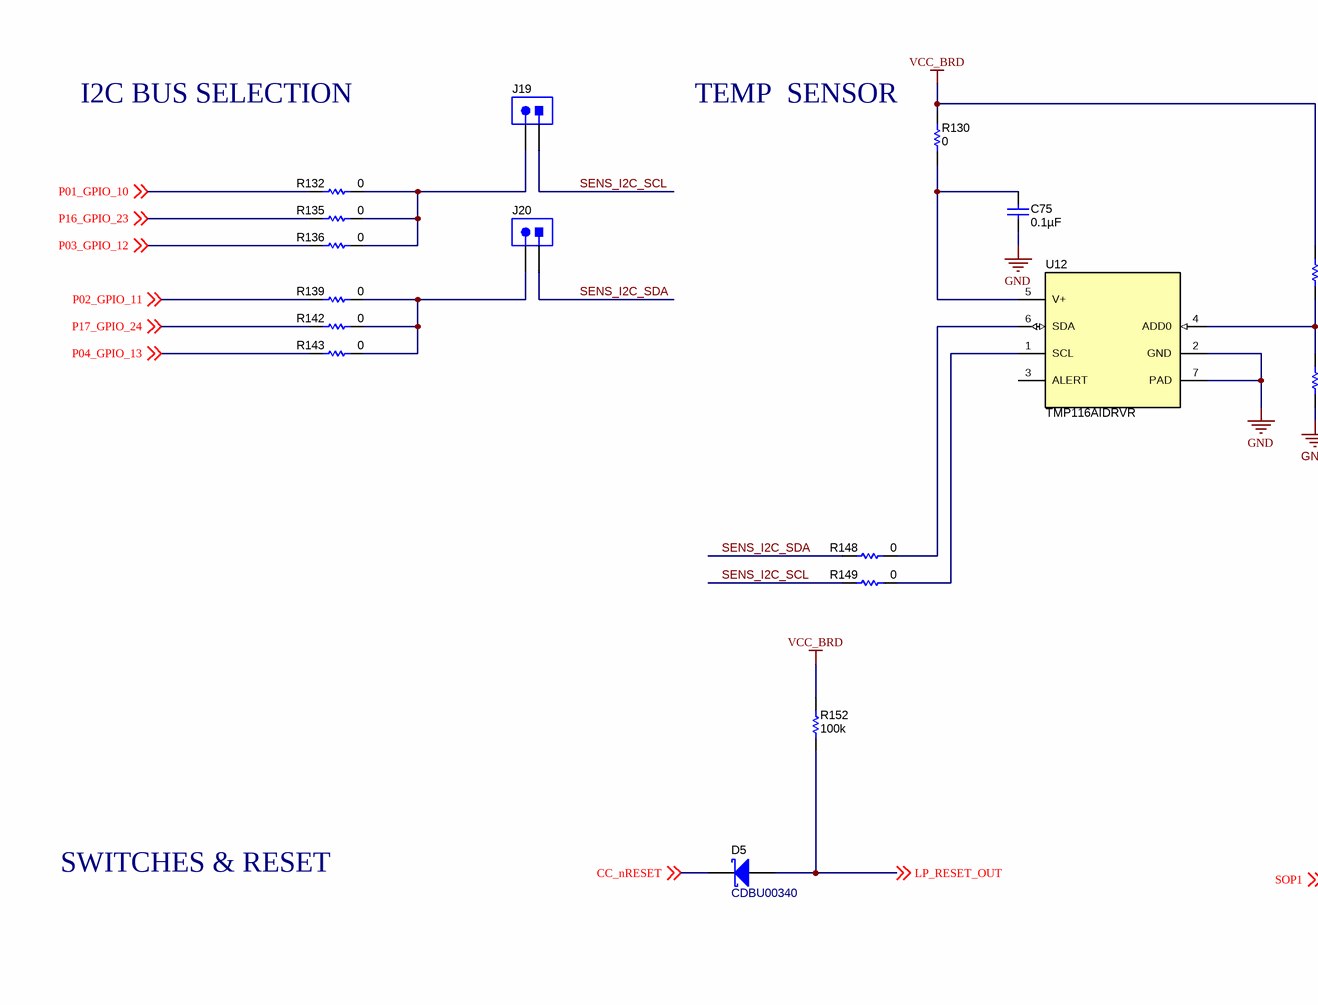
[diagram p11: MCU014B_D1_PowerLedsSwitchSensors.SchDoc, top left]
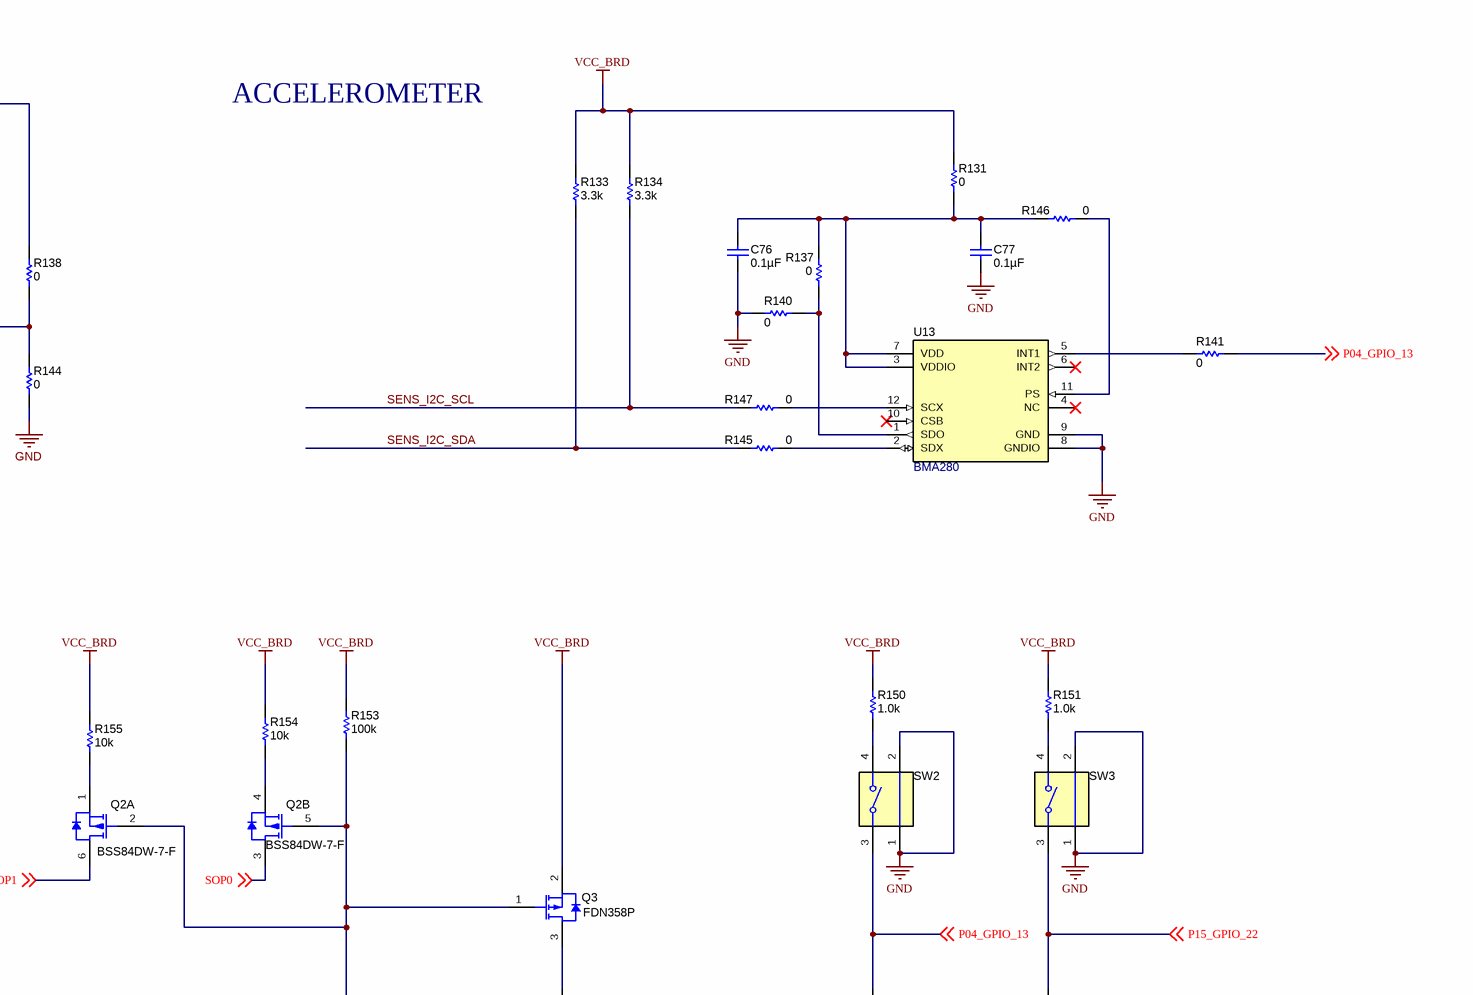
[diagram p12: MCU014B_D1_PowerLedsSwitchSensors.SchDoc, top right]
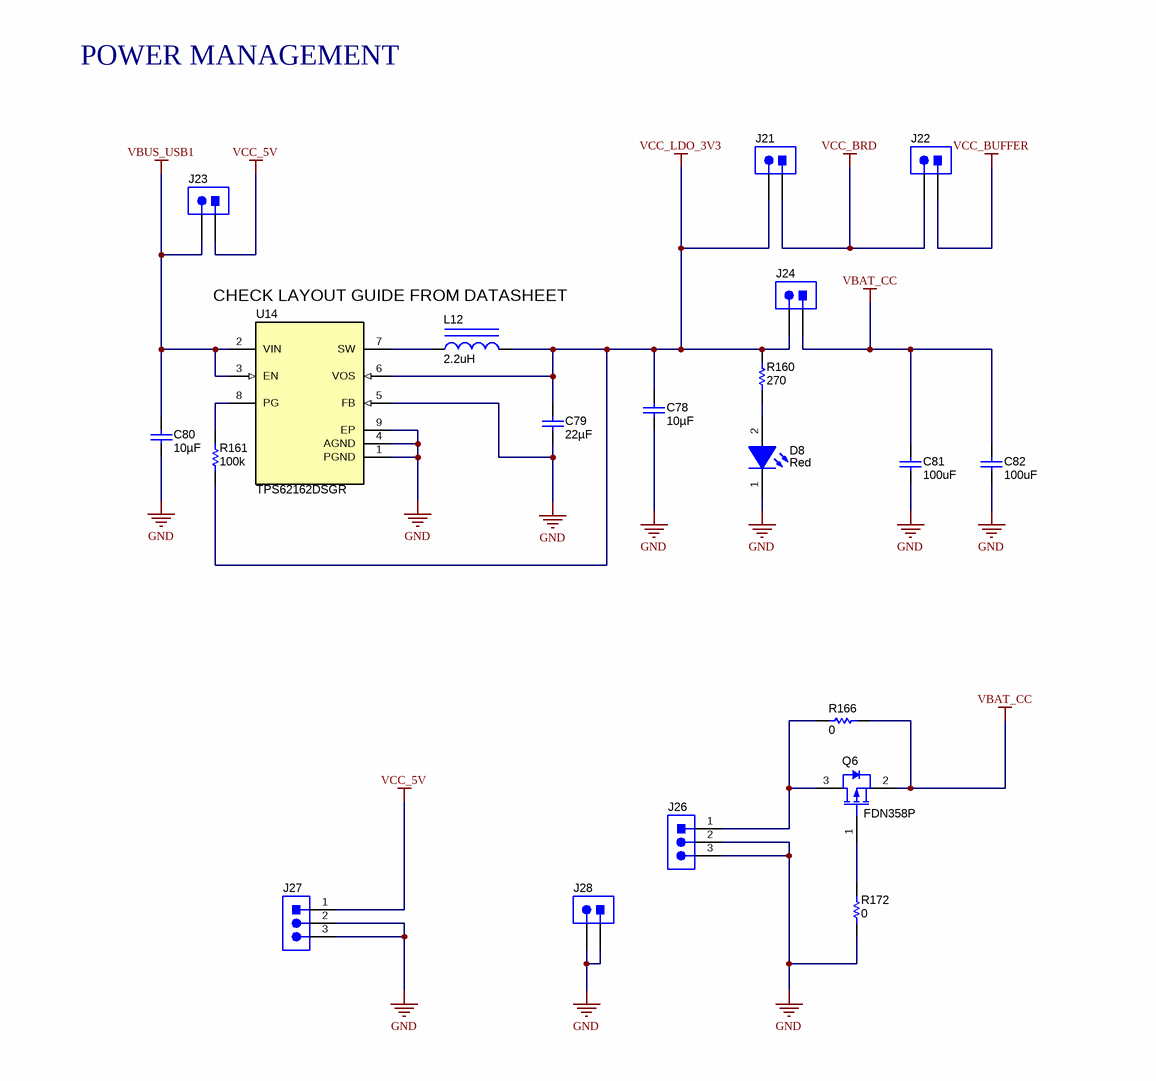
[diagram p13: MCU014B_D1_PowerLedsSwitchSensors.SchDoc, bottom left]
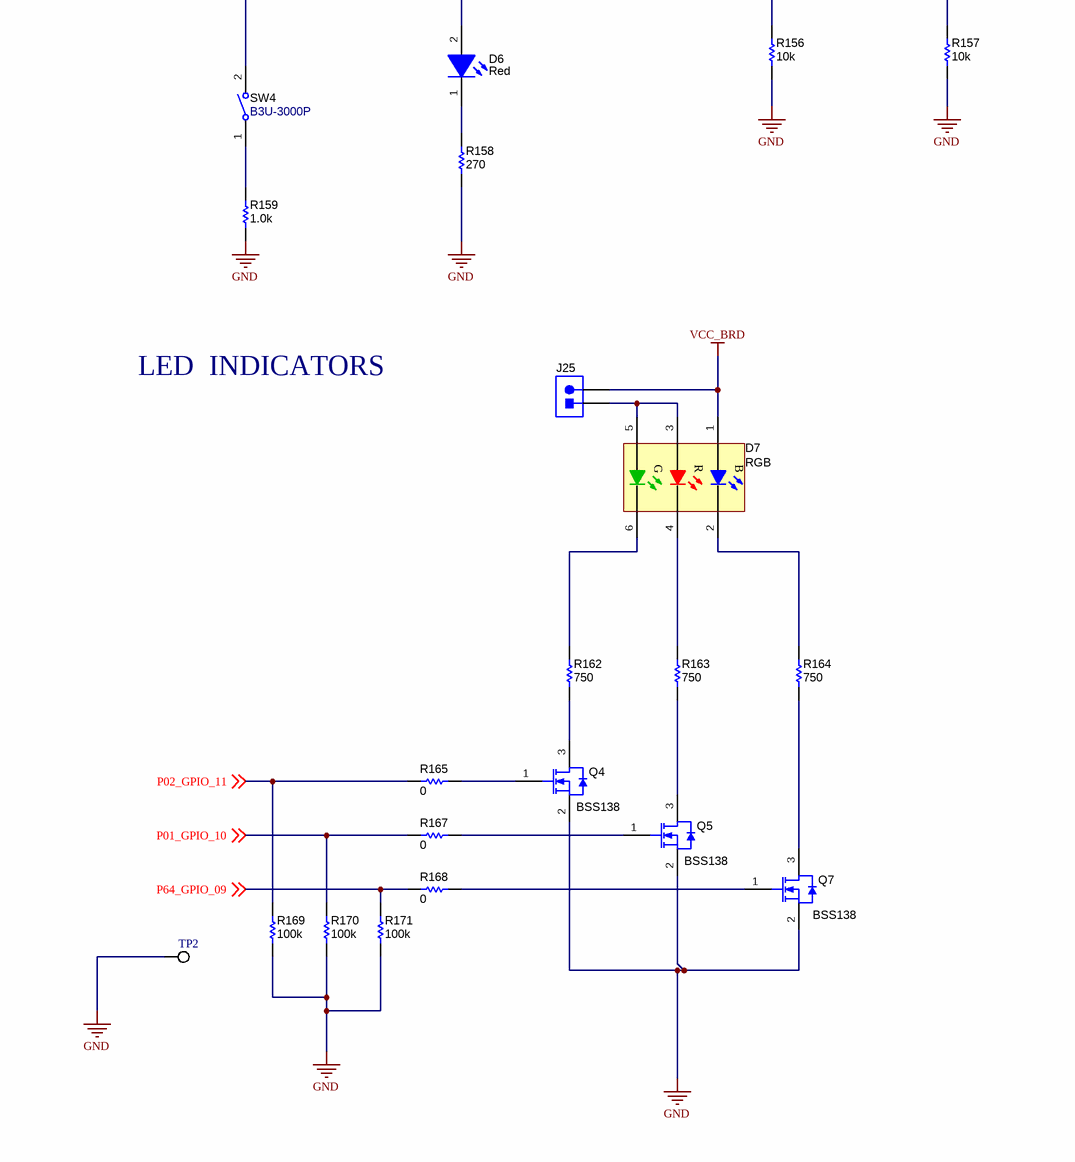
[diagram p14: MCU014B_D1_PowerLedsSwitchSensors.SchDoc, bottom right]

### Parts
C75  ValueDisplayed: 0.1µF  [0402S]  (hidden comment: CL05B104KO5NNNC)
C76  ValueDisplayed: 0.1µF  [0402S]  (hidden comment: CL05B104KO5NNNC)
C77  ValueDisplayed: 0.1µF  [0402S]  (hidden comment: CL05B104KO5NNNC)
C78  ValueDisplayed: 10µF  [0805]  (hidden comment: CL21A106KPFNNNE)
C79  ValueDisplayed: 22µF  [0805]  (hidden comment: CL21A226KOQNNNE)
C80  ValueDisplayed: 10µF  [0805]  (hidden comment: CL21A106KPFNNNE)
C81  ValueDisplayed: 100uF  [1206_180M]  (hidden comment: CMP-0008934-2)
C82  ValueDisplayed: 100uF  [1206_180]  (hidden comment: CMP-0008934-2)
D5  CDBU00340  [SOD-523F]
D6  value Red  [SML-31_Red]  (hidden comment: CMP-0002871-1)
D7  Color: RGB  [EAST1616_RGB]  (hidden comment: CMP-0003017-2)
D8  value Red  [SML-31_Red]  (hidden comment: CMP-0002871-1)
J19  CMP-0054794-1  [WURTH_61300211121]  (value not drawn)
J20  CMP-0054794-1  [WURTH_61300211121]  (value not drawn)
J21  CMP-0054794-1  [WURTH_61300211121]  (value not drawn)
J22  CMP-0054794-1  [WURTH_61300211121]  (value not drawn)
J23  CMP-0054794-1  [WURTH_61300211121]  (value not drawn)
J24  CMP-0054794-1  [WURTH_61300211121]  (value not drawn)
J25  CMP-0054794-1  [WURTH_61300211121]  (value not drawn)
J26  CMP-0054796-1  [WURTH_61300311121]  (value not drawn)
J27  CMP-0054796-1  [WURTH_61300311121]  (value not drawn)
J28  CMP-0054794-1  [WURTH_61300211121]  (value not drawn)
L12  ValueDisplayed: 2.2uH  [0805]  (hidden comment: CMP-0059580-1)
Q2  PartNumber: BSS84DW-7-F  [SOT-363]  (hidden comment: CMP-0000014-2)  (parts A,B of 2)
Q3  PartNumber: FDN358P  [SSOT-3]  (hidden comment: CMP-0000059-2)
Q4  PartNumber: BSS138  [SOT-23]  (hidden comment: CMP-0000755-1)
Q5  PartNumber: BSS138  [SOT-23]  (hidden comment: CMP-0000755-1)
Q6  PartNumber: FDN358P  [SSOT-3]  (hidden comment: CMP-0000059-2)
Q7  PartNumber: BSS138  [SOT-23]  (hidden comment: CMP-0000755-1)
R130  ValueDisplayed: 0  [0402]  (hidden comment: CMP-0026992-2)
R131  ValueDisplayed: 0  [0402]  (hidden comment: CMP-0026992-2)
R132  ValueDisplayed: 0  [0402]  (hidden comment: CMP-0026992-2)
R133  ValueDisplayed: 3.3k  [0402]  (hidden comment: CMP-0026918-5)
R134  ValueDisplayed: 3.3k  [0402]  (hidden comment: CMP-0026918-5)
R135  ValueDisplayed: 0  [0402]  (hidden comment: CMP-0026992-2)
R136  ValueDisplayed: 0  [0402]  (hidden comment: CMP-0026992-2)
R137  ValueDisplayed: 0  [0402]  (hidden comment: CMP-0026992-2)
R138  ValueDisplayed: 0  [0402]  (hidden comment: CMP-0026992-2)
R139  ValueDisplayed: 0  [0402]  (hidden comment: CMP-0026992-2)
R140  ValueDisplayed: 0  [0402]  (hidden comment: CMP-0026992-2)
R141  ValueDisplayed: 0  [0805_HV]  (hidden comment: CMP-0020616-2)
R142  ValueDisplayed: 0  [0402]  (hidden comment: CMP-0026992-2)
R143  ValueDisplayed: 0  [0402]  (hidden comment: CMP-0026992-2)
R144  ValueDisplayed: 0  [0402]  (hidden comment: CMP-0026992-2)
R145  ValueDisplayed: 0  [0402]  (hidden comment: CMP-0026992-2)
R146  ValueDisplayed: 0  [0402]  (hidden comment: CMP-0026992-2)
R147  ValueDisplayed: 0  [0402]  (hidden comment: CMP-0026992-2)
R148  ValueDisplayed: 0  [0402]  (hidden comment: CMP-0026992-2)
R149  ValueDisplayed: 0  [0402]  (hidden comment: CMP-0026992-2)
R150  ValueDisplayed: 1.0k  [0402]  (hidden comment: CMP-0026852-3)
R151  ValueDisplayed: 1.0k  [0402]  (hidden comment: CMP-0026852-3)
R152  ValueDisplayed: 100k  [0402]  (hidden comment: CMP-0026823-3)
R153  ValueDisplayed: 100k  [0402]  (hidden comment: CMP-0026659-1)
R154  ValueDisplayed: 10k  [0402]  (hidden comment: CMP-0026825-5)
R155  ValueDisplayed: 10k  [0402]  (hidden comment: CMP-0026825-5)
R156  ValueDisplayed: 10k  [0402]  (hidden comment: CMP-0026825-5)
R157  ValueDisplayed: 10k  [0402]  (hidden comment: CMP-0026825-5)
R158  ValueDisplayed: 270  [0603]  (hidden comment: CMP-0025765-4)
R159  ValueDisplayed: 1.0k  [0402]  (hidden comment: CMP-0026852-3)
R160  ValueDisplayed: 270  [0603]  (hidden comment: CMP-0025765-4)
R161  ValueDisplayed: 100k  [0402]  (hidden comment: CMP-0026823-3)
R162  ValueDisplayed: 750  [0603]  (hidden comment: CMP-0025939-3)
R163  ValueDisplayed: 750  [0603]  (hidden comment: CMP-0025939-3)
R164  ValueDisplayed: 750  [0603]  (hidden comment: CMP-0025939-3)
R165  ValueDisplayed: 0  [0402]  (hidden comment: CMP-0026992-2)
R166  ValueDisplayed: 0  [0603]  (hidden comment: CMP-0025874-3)
R167  ValueDisplayed: 0  [0402]  (hidden comment: CMP-0026992-2)
R168  ValueDisplayed: 0  [0402]  (hidden comment: CMP-0026992-2)
R169  ValueDisplayed: 100k  [0402]  (hidden comment: CMP-0026823-3)
R170  ValueDisplayed: 100k  [0402]  (hidden comment: CMP-0026823-3)
R171  ValueDisplayed: 100k  [0402]  (hidden comment: CMP-0026823-3)
R172  ValueDisplayed: 0  [0402]  (hidden comment: CMP-0026992-2)
SW2  CMP-0002328-1  [SW_1188E]  (value not drawn)
SW3  CMP-0002328-1  [SW_1188E]  (value not drawn)
SW4  B3U-3000P  [SW_B3U-3000P]
TP2  5015  [Testpoint_Keystone_Miniature]  (value not drawn)
U12  TMP116AIDRVR  [DRV0006A]
U13  BMA280  [12LGA]
U14  PartNumber: TPS62162DSGR  [DSG0008A]  (hidden comment: CMP-0037789-2)

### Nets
GND: C75.2 C76.2 C77.2 C78.2 C79.2 C80.2 C81.2 C82.2 D8.1(K) J26.2 J26.3 J27.2 J27.3 J28.1 J28.2 Q4.2(S) Q5.2(S) Q7.2(S) R140.1 R144.1 R156.2 R157.2 R158.1 R159.1 R169.2 R170.2 R171.2 R172.1 SW2.1 SW2.2 SW3.1 SW3.2 TP2.1 U12.2(GND) U12.7(PAD) U13.8(GNDIO) U13.9(GND) U14.1(PGND) U14.4(AGND) U14.5(FB) U14.9(EP)
VBAT_CC: C81.1 C82.1 J24.1 Q6.2(S) R166.2
VBUS_USB1: C80.1 J23.2 U14.2(VIN) U14.3(EN)
VCC_5V: J23.1 J27.1
VCC_BRD: D7.1(A) J21.1 J22.2 J25.2 Q3.2(S) R130.2 R131.2 R133.1 R134.1 R138.2 R150.1 R151.1 R152.1 R153.2 R154.2 R155.2
VCC_BUFFER: J22.1
VCC_LDO_3V3: C78.1 C79.1 J21.2 J24.2 L12.2 R160.1 R161.2 U14.6(VOS)
CC_nRESET: D5.1(K) ; off-sheet CC_nRESET
LP_RESET_OUT: D5.2(A) R152.2 ; off-sheet LP_RESET_OUT
P01_GPIO_10: R132.1 R167.1 R170.1 ; off-sheet P01_GPIO_10
P02_GPIO_11: R139.1 R165.1 R169.1 ; off-sheet P02_GPIO_11
P03_GPIO_12: R136.1 ; off-sheet P03_GPIO_12
P04_GPIO_13: R141.2 R143.1 R156.1 SW2.3 ; off-sheet P04_GPIO_13
P15_GPIO_22: R157.1 SW3.3 ; off-sheet P15_GPIO_22
P16_GPIO_23: R135.1 ; off-sheet P16_GPIO_23
P17_GPIO_24: R142.1 ; off-sheet P17_GPIO_24
P64_GPIO_09: R168.1 R171.1 ; off-sheet P64_GPIO_09
SENS_I2C_SCL: J19.1 R134.2 R147.1 R149.1
SENS_I2C_SDA: J20.1 R133.2 R145.1 R148.1
SOP0: Q2.3(D) ; off-sheet SOP0
SOP1: Q2.6(D) ; off-sheet SOP1
NetC75_1: C75.1 R130.1 U12.5(V+)
NetC76_1: C76.1 C77.1 R131.1 R137.2 R146.2 U13.3(VDDIO) U13.7(VDD)
NetD6_1: D6.1(K) R158.2
NetD6_2: D6.2(A) Q3.3(D)
NetD7_2: D7.2(K) R164.2
NetD7_3: D7.3(A) D7.5(A) J25.1
NetD7_4: D7.4(K) R163.2
NetD7_6: D7.6(K) R162.2
NetD8_2: D8.2(A) R160.2
NetJ19_2: J19.2 R132.2 R135.2 R136.2
NetJ20_2: J20.2 R139.2 R142.2 R143.2
NetJ26_1: J26.1 Q6.3(D) R166.1
NetL12_1: L12.1 U14.7(SW)
NetQ2_1: Q2.1(S) R155.1
NetQ2_2: Q2.2(G) Q2.5(G) Q3.1(G) R153.1 SW4.2
NetQ2_4: Q2.4(S) R154.1
NetQ4_1: Q4.1(G) R165.2
NetQ4_3: Q4.3(D) R162.1
NetQ5_1: Q5.1(G) R167.2
NetQ5_3: Q5.3(D) R163.1
NetQ6_1: Q6.1(G) R172.2
NetQ7_1: Q7.1(G) R168.2
NetQ7_3: Q7.3(D) R164.1
NetR137_1: R137.1 R140.2 U13.1(SDO)
NetR138_1: R138.1 R144.2 U12.4(ADD0)
NetR141_1: R141.1 U13.5(INT1)
NetR145_2: R145.2 U13.2(SDX)
NetR146_1: R146.1 U13.11(PS)
NetR147_2: R147.2 U13.12(SCX)
NetR148_2: R148.2 U12.6(SDA)
NetR149_2: R149.2 U12.1(SCL)
NetR150_2: R150.2 SW2.4
NetR151_2: R151.2 SW3.4
NetR159_2: R159.2 SW4.1
NetR161_1: R161.1 U14.8(PG)

Not connected (* = marked no-connect by the designer): U12 3(ALERT); U13 4(NC)* 6(INT2)* 10(CSB)*

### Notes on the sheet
- I2C BUS SELECTION
- TEMP  SENSOR
- ACCELEROMETER
- SWITCHES & RESET
- POWER MANAGEMENT
- CHECK LAYOUT GUIDE FROM DATASHEET
- LED  INDICATORS

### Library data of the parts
C75-C77 = CMP-0085850-1: CAP, CERM, 0.1 µF, 16 V,+/- 10%, X7R, 0402; Manufacturer: Walsin; Alternate PartNumber: C1005X5R1A104K050BA; Polarized: N; Value: 0.1uF; U/M: EA; Cap_F: 100nF; VDC_V: 16V; TaMin_C: -55°C; TaMax_C: 125°C; Cap_Case: 0402; SizeAreaWB_mm2: 3; SizeZ_mm: 0.6; SizeX_mm: 1; SizeY_mm: 0.5; AEC Category: Q200
C78 C80 = CMP-0084772-1: CAP, CERM, 10 µF, 10 V,+/- 10%, X5R, 0805; Manufacturer: Samsung Electro-Mechanics; Alternate PartNumber: GRM21BR61A106KE19L; Polarized: N; Value: 10uF; U/M: EA; VDC_V: 10V; TaMin_C: -55°C; TaMax_C: 85°C; SizeAreaWB_mm2: 6.75; SizeZ_mm: 1.45; SizeX_mm: 2; SizeY_mm: 1.25; SizeArea_mm2: 2.5; AEC Category: Q200
C79 = CMP-0085852-1: CAP, CERM, 22 µF, 16 V,+/- 10%, X5R, 0805; Manufacturer: Samsung Electro-Mechanics; Alternate PartNumber: C2012X5R1C226K125AC; Polarized: N; Value: 22uF; U/M: EA; VDC_V: 16V; TaMin_C: -55°C; TaMax_C: 85°C; AEC Category: Q200; SizeAreaWB_mm2: 6.75; SizeZ_mm: 1.45; SizeX_mm: 2; SizeY_mm: 1.25; SizeArea_mm2: 2.5
C81 C82 = CMP-0008934-2: CAP, CERM, 100 uF, 6.3 V, +/- 20%, X5R, 1206; PartNumber: GRM31CR60J107ME39L; Manufacturer: MuRata; Alternate PartNumber: CL31A107MQHNNNE; Alternate Manufacturer: SAMSUNG; Polarized: N; CompType: Capacitor; Value: 100uF; U/M: EA; Cap_F: 100µF; ESR_ohm: 3m; Value1: 0.003 ohm; VDC_V: 6.3V; TaMin_C: -55°C; TaMax_C: 85°C; Cap_Case: 1206; SizeAreaWB_mm2: 10.92; SizeZ_mm: 1.8; SizeX_mm: 3.2; SizeY_mm: 1.6; SizeArea_mm2: 5.12; AEC Category: Q200
D5 = CMP-0081923-2: Diode, Schottky, 45 V, 0.03 A, SOD-523F; Manufacturer: Comchip Technology; Alternate PartNumber: CD0603-B00340; Vf_V: 370mV; Value: 45V; Value1: 0.03A; Value2: 0.37V; Io_A: 30mA; TJmax_C: 125°C; SizeAreaWB_mm2: 5.13; SizeZ_mm: 0.85; SizeX_mm: 1.7; SizeY_mm: 0.9; SizeArea_mm2: 1.53; AEC Qualified: N; AEC Category: Q101
D6 D8 = CMP-0002871-1: LED, Red, SMD; Manufacturer: Everlight; PartNumber: 19-217/R6C-AL1M2VY/3T; Alternate Manufacturer: Rohm; Alternate PartNumber: SML-311UTT86; Type: AlInGaP; Vf_V: 1.8V; Io_A: 2mA; Value1: W; U/M: EA
D7 = CMP-0003017-2: LED, Rgb, SMD; PartNumber: EAST1616RGBA8; Manufacturer: Everlight; Alternate PartNumber: 19-337-R6GHBHC-C02-2T; Type: InGaN; Vf_V: 3.7V; Io_A: 25mA; Vr_V: 5V; Ir_A: 50µA; Tjmax_C: 85°C; Value1: W; Angle: 120; SizeAreaWB_mm2: 6.76; SizeArea_mm2: 2.56; SizeX_mm: 1.6; SizeZ_mm: 0.45; U/M: EA
J19-J25 J28 = CMP-0054794-1: as J12 on sheet MCU014B_D1_EngineArea
J26 J27 = CMP-0054796-1: as J14-J17 on sheet MCU014B_D1_EngineArea
L12 = CMP-0059580-1: Inductor, Wirewound, 2.2 uH, 1 A, 0.143 ohm, SMD; PartNumber: BRC2012T2R2MD; Manufacturer: Taiyo Yuden; Alternate PartNumber: ----; Value: 2.2uH; Ind_H: 2.2µH; Imax_A: 1A; Irms: 1A @ 40C rise; Isat: 1.1A @ 30% inductance drop; DCR_ohm: 1.43d; AEC Category: Q200; Green_Lifecycle: Active; SizeAreaWB_mm2: 6.75; Green_REACh: Passed; SizeZ_mm: 1.45; SizeX_mm: 2; SizeY_mm: 1.25; SizeArea_mm2: 2.5
Q2 = CMP-0000014-2: MOSFET, 2-CH, P-CH, -50 V, -0.13 A, AEC-Q101, SOT-363; Manufacturer: Diodes Inc.; Alternate Manufacturer: ----; U/M: EA; ChType: P; Value: -50V; Vgs_V: -20V; IdsMax_A: -1.3dA; AEC Category: Q101; AEC Qualified: Y; SizeZ_mm: 1.1; SizeX_mm: 2.2; SizeArea_mm2: 4.84; SizeAreaWB_mm2: 10.24
Q3 Q6 = CMP-0000059-2: MOSFET, P-CH, -30 V, -1.5 A, SSOT-3; Manufacturer: Fairchild Semiconductor; Alternate Manufacturer: ----; U/M: EA; ChType: P; Value: -30V; Value1: 0; Rdson45_ohm: 2d; Value2: 4 nC; QgTyp_nC: 4; Vgs_V: -20V; IdsMax_A: -1.5A; SizeZ_mm: 1.12; SizeX_mm: 2.92; SizeY_mm: 2.52; SizeArea_mm2: 7.3584; AEC Category: Q101; SizeAreaWB_mm2: 13.7984
Q4 Q5 Q7 = CMP-0000755-1: MOSFET, N-CH, 50 V, 0.22 A, SOT-23; Manufacturer: Fairchild Semiconductor; Alternate Manufacturer: ON; Alternate PartNumber: BSS138LT1G; U/M: EA; ChType: N; Value: 50V; Rdson45_ohm: 6; Value2: 1.7 nC; QgTyp_nC: 1.7; Vgs_V: 20V; IdsMax_A: 2.2dA; SizeAreaWB_mm2: 14; SizeArea_mm2: 7.5; SizeX_mm: 2.5; SizeY_mm: 3; SizeZ_mm: 1.1; AEC Category: Q101
R130-R132 R135-R140 R142-R149 R165 R167 R168 R172 = CMP-0026992-2: as R47 on sheet MCU014B_D1_EngineArea
R133 R134 = CMP-0026918-5: RES, 3.3 k, 5%, 0.063 W, AEC-Q200 Grade 0, 0402; PartNumber: CRCW04023K30JNED; Manufacturer: Vishay-Dale; Alternate Manufacturer: YAGEO; Alternate PartNumber: RC0402JR-073K3L; Value: 3.3k; Value_Code: 3k30; Power_W: 63mW; Value2: 0.063W; VDC_V: 50V; TempCo: 200 ppm/C; EIA_Code: E24; SizeX_mm: 1; SizeY_mm: 0.5; SizeZ_mm: 0.6; AEC Qualified: Y; AEC Category: Q200; AEC Grade: 0
R141 = CMP-0020616-2: RES, 0, 5%, 0.125 W, 0805; PartNumber: ERJ-6GEY0R00V; Manufacturer: Panasonic; Alternate Manufacturer: ----; CompType: Resistor; Value: 0; Value_Code: 0000; Power_W: 125mW; Value2: 0.125W; VDC_V: 150V; TempCo: 600 ppm/C; EIA_Code: E24; U/M: EA; AEC Category: Q200; SizeX_mm: 2; SizeY_mm: 1.25; SizeZ_mm: 1.45; SizeArea_mm2: 2.5
R150 R151 R159 = CMP-0026852-3: RES, 1.0 k, 5%, 0.063 W, AEC-Q200 Grade 0, 0402; PartNumber: CRCW04021K00JNED; Manufacturer: Vishay-Dale; Alternate Manufacturer: YAGEO; Alternate PartNumber: RC0402JR-071KL; Value: 1.0k; Res_ohm: 1k; Value_Code: 1k00; Power_W: 63mW; Value2: 0.063W; VDC_V: 50V; TempCo: 200 ppm/C; EIA_Code: E24; SizeX_mm: 1; SizeY_mm: 0.5; SizeZ_mm: 0.6; AEC Qualified: Y; AEC Category: Q200; AEC Grade: 0
R152 R161 = CMP-0026823-3: as R44-R46 on sheet MCU014B_D1_EngineArea
R153 = CMP-0026659-1: RES, 100 k, 1%, 0.1 W, 0402; PartNumber: ERJ-2RKF1003X; Manufacturer: Panasonic; Alternate Manufacturer: YAGEO; Alternate PartNumber: RC0402FR-07100KL; Value: 100k; Power_W: 100mW; Value2: 0.1W; VDC_V: 50V; TempCo: 100 ppm/C; EIA_Code: E96; U/M: EA; AEC Category: Q200; SizeX_mm: 1; SizeY_mm: 0.5; SizeZ_mm: 0.6
R154 R155 = CMP-0026825-5: RES, 10 k, 5%, 0.063 W, AEC-Q200 Grade 0, 0402; PartNumber: CRCW040210K0JNED; Manufacturer: Vishay-Dale; Alternate Manufacturer: YAGEO; Alternate PartNumber: RC0402JR-0710KL; CompType: Resistor; Value: 10k; Value_Code: 10k0; Power_W: 63mW; Value2: 0.063W; VDC_V: 50V; TempCo: 200 ppm/C; EIA_Code: E24; SizeX_mm: 1; SizeY_mm: 0.5; SizeZ_mm: 0.6; AEC Qualified: Y; AEC Category: Q200; AEC Grade: 0
R156 R157 = CMP-0026825-5: as R59 on sheet MCU014B_D1_EngineArea
R158 = CMP-0025765-4: RES, 270, 5%, 0.1 W, AEC-Q200 Grade 0, 0603; PartNumber: CRCW0603270RJNEA; Manufacturer: Vishay-Dale; Alternate Manufacturer: YAGEO; Alternate PartNumber: RC0603JR-07270RL; CompType: Resistor; Value: 270; Value_Code: 270R; Power_W: 100mW; Value2: 0.1W; VDC_V: 75V; TempCo: 200 ppm/C; EIA_Code: E24; SizeX_mm: 1.6; SizeY_mm: 0.8; SizeZ_mm: 1; SizeArea_mm2: 1.28; AEC Qualified: Y; AEC Category: Q200; AEC Grade: 0
R160 = CMP-0025765-4: RES, 270, 5%, 0.1 W, AEC-Q200 Grade 0, 0603; PartNumber: CRCW0603270RJNEA; Manufacturer: Vishay-Dale; Alternate Manufacturer: YAGEO; Alternate PartNumber: RC0603JR-07270RL; Value: 270; Value_Code: 270R; Power_W: 100mW; Value2: 0.1W; VDC_V: 75V; TempCo: 200 ppm/C; EIA_Code: E24; SizeX_mm: 1.6; SizeY_mm: 0.8; SizeZ_mm: 1; SizeArea_mm2: 1.28; AEC Qualified: Y; AEC Category: Q200; AEC Grade: 0
R162-R164 = CMP-0025939-3: RES, 750, 5%, 0.1 W, 0603; PartNumber: RC0603JR-07750RL; Manufacturer: Yageo America; Alternate Manufacturer: ----; Value: 750; Value_Code: 750R; Power_W: 100mW; Value2: 0.1W; VDC_V: 50V; TempCo: 100 ppm/C; SizeArea_mm2: 1.28; SizeX_mm: 1.6; SizeY_mm: 0.8; SizeZ_mm: 1; EIA_Code: E24; U/M: EA; AEC Category: Q200
R166 = CMP-0025874-3: as R64 on sheet MCU014B_D1_HostInterface_ADC
R169-R171 = CMP-0026823-3: as R41 on sheet MCU014B_D1_EngineArea
SW2 SW3 = CMP-0002328-1: Switch, SPST, 0.05 A, 12 VDC, SMD; PartNumber: 1188E-1K2-V-TR; Manufacturer: Diptronics; Alternate Manufacturer: ----; VDC_V: 12V; PositionCount: 1; CurrentRating_mA: 50A; SizeAreaWB_mm2: 53.9; SizeArea_mm2: 27.3; SizeX_mm: 7.8; SizeY_mm: 3.5
SW4 = CMP-0076764-1: Switch, SPST-NO, Off-Mom, 0.05 A, 12 VDC, SMT; Manufacturer: Omron Electronic Components; VDC_V: 12V; PositionCount: 1.0; CurrentRating_mA: 50A; SizeAreaWB_mm2: 21.0; SizeArea_mm2: 12.8; SizeX_mm: 3.2; SizeY_mm: 4.0; SizeZ_mm: 1.35
TP2 = CMP-0055152-1: Test Point, Miniature, SMT; Manufacturer: Keystone; Alternate Manufacturer: ----; CNHeader: FALSE; Green_Lifecycle: Active; Green_REACh: Passed; CT: TRUE
U12 = CMP-0013432-6: High-Accuracy, Low-Power, Digital Temperature Sensor with SMBus and Two-Wire Serial Interface, DRV0006A (WSON-6); Alternate PartNumber: TMP116AIDRVT; Manufacturer: Texas Instruments; SizeArea_mm2: 4; SizeAreaWB_mm2: 9; SizeX_mm: 2; SizeZ_mm: 0.8; CompType: IC; U/M: EA
U13 = CMP-0004812-1: 14 Bit, Digital, Triaxial Acceleration Sensor with Intelligent On-Chip Motion-Triggered Interrupt Controller, 12LGA; Manufacturer: Bosch Solar Energy
U14 = CMP-0037789-2: Buck Step Down Regulator with 3 to 17 V Input and 3.3 V Output, -40 to 85 degC, 8-Pin WSON (DSG), Green (RoHS & no Sb/Br); Manufacturer: Texas Instruments; Alternate PartNumber: ----; Duty Cycle(Max)(%): 100; Iout(Max)(A): 1; Iq(Typ)(mA): 0.017; Preset Vout(V): 3.3; Rating: Catalog; SubFamily: Step-Down Regulator; Switch Current Limit(Typ)(A): 1.8; Synchronous Rectification: TRUE; Vin(Max)(V): 17; Vin(Min)(V): 3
